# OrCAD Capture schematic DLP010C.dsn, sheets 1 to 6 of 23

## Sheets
1 PAGE23- IMPORTANT NOTICE
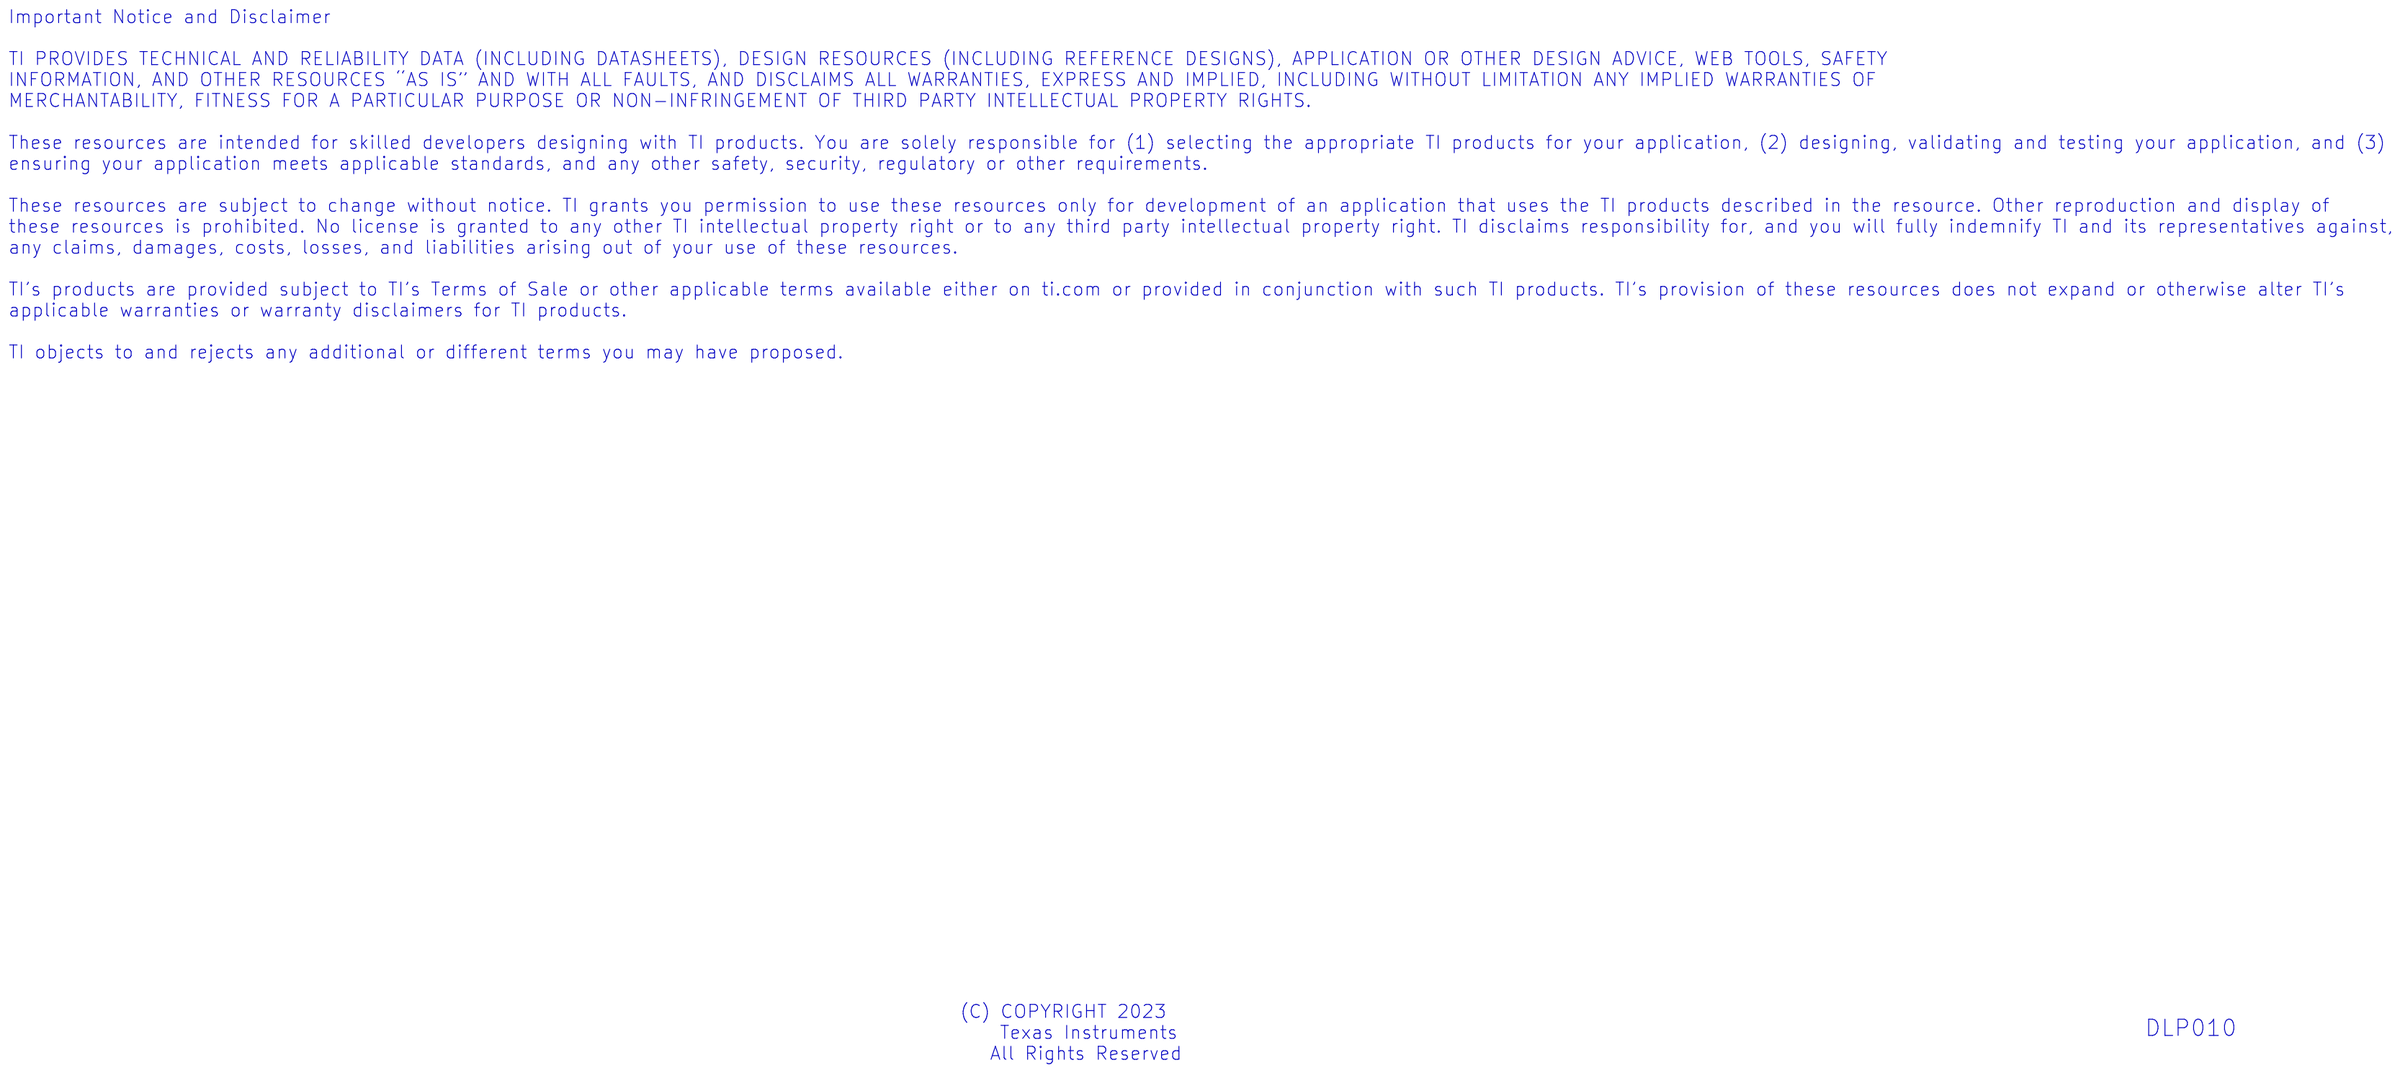
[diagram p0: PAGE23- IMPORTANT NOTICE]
2 PAGE 01 - TITLE PAGE: title: DLP010A - DLPLCRC410EVM Board
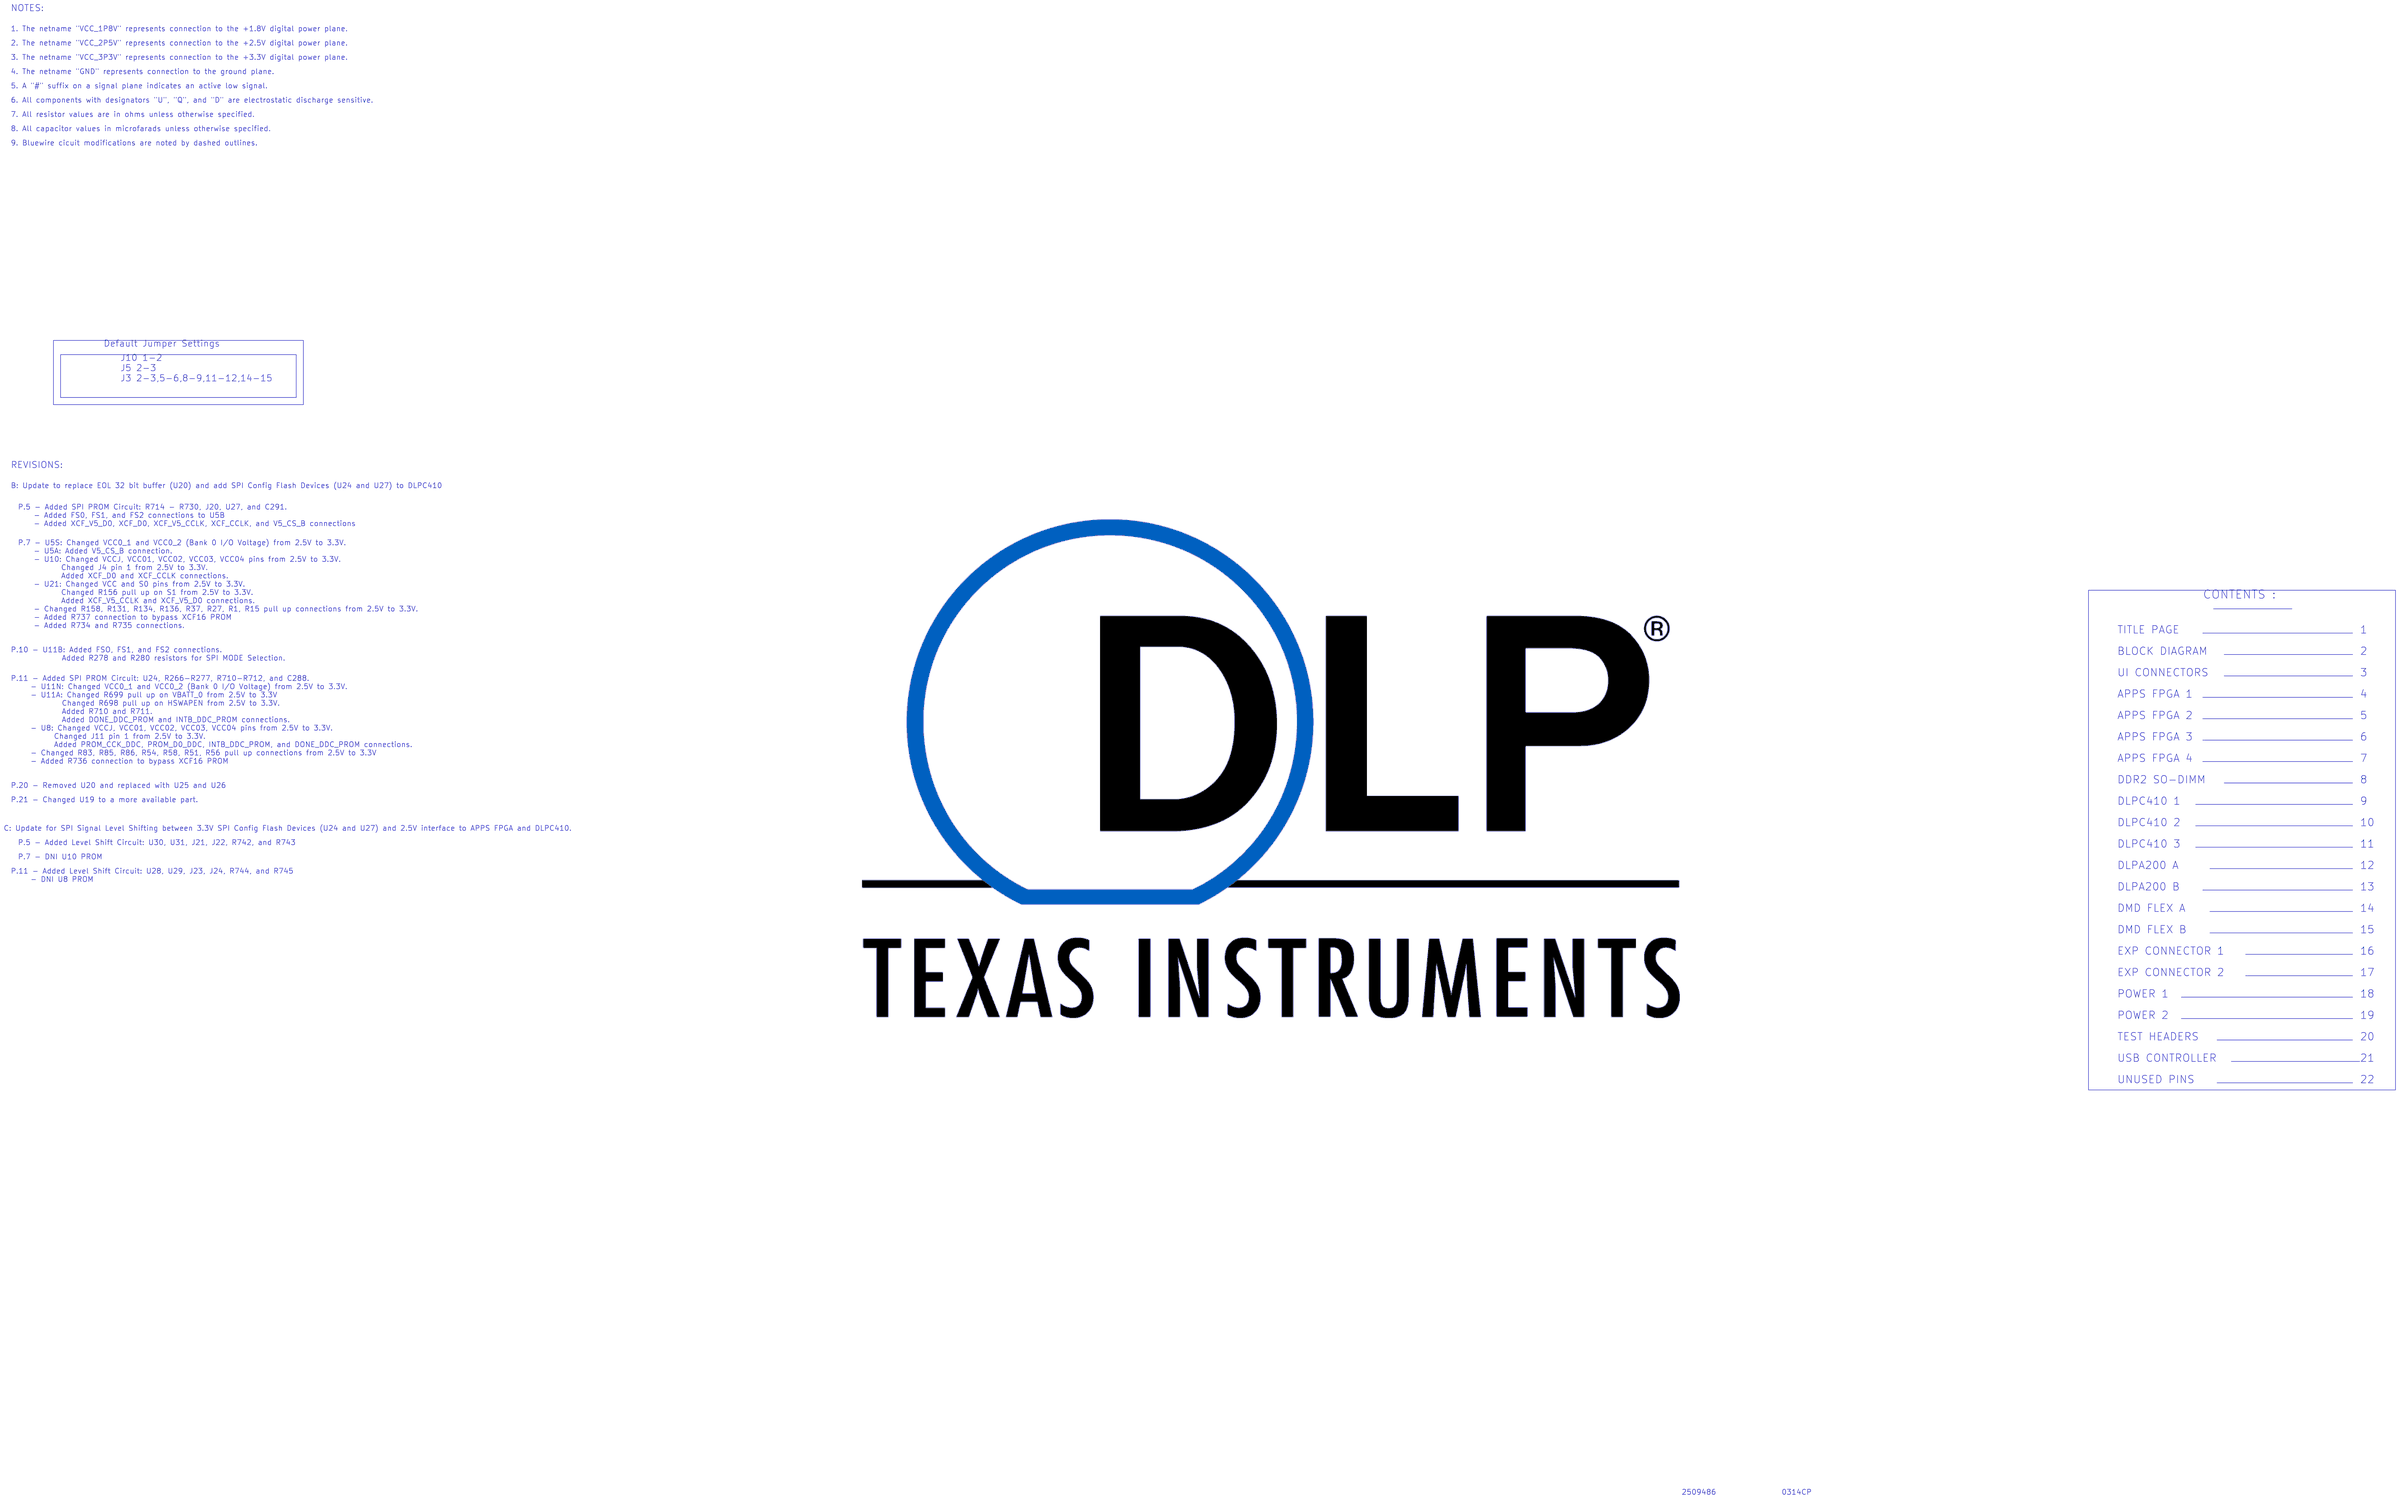
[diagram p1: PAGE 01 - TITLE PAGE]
3 PAGE 02 - BLOCK DIAGRAM
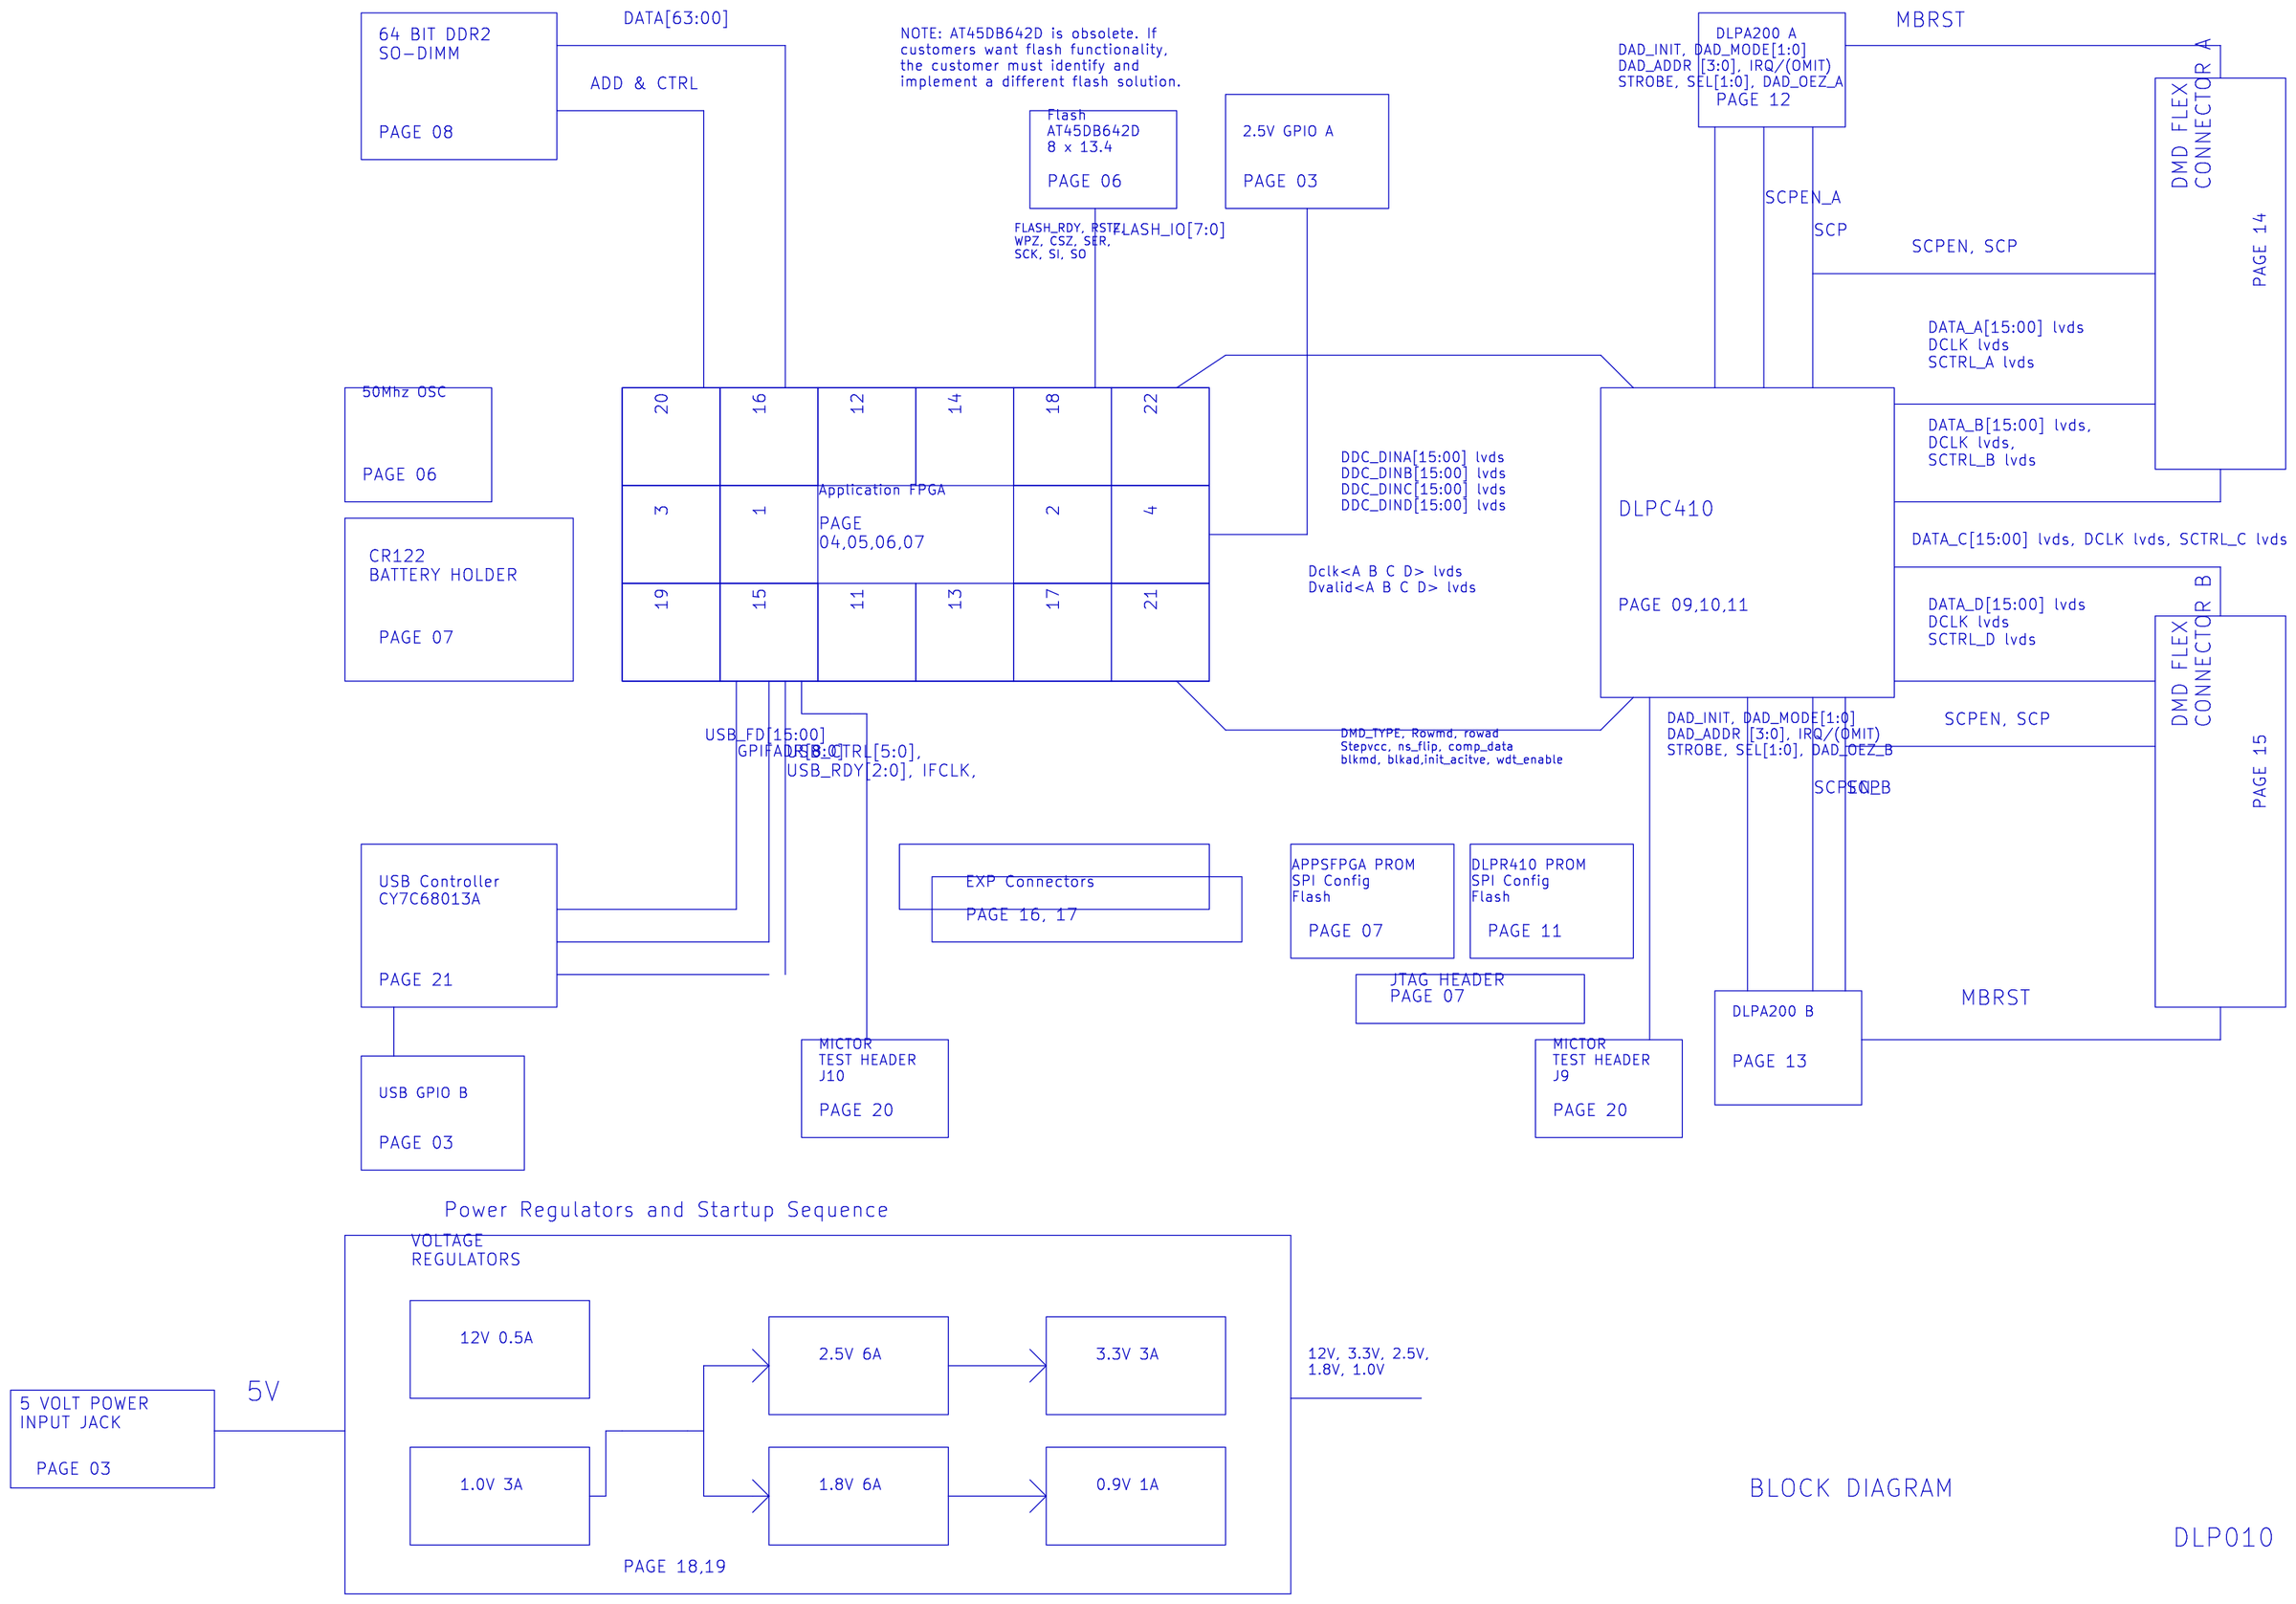
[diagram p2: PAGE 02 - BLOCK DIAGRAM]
4 PAGE 03 - UI CONNECTORS: size Custom
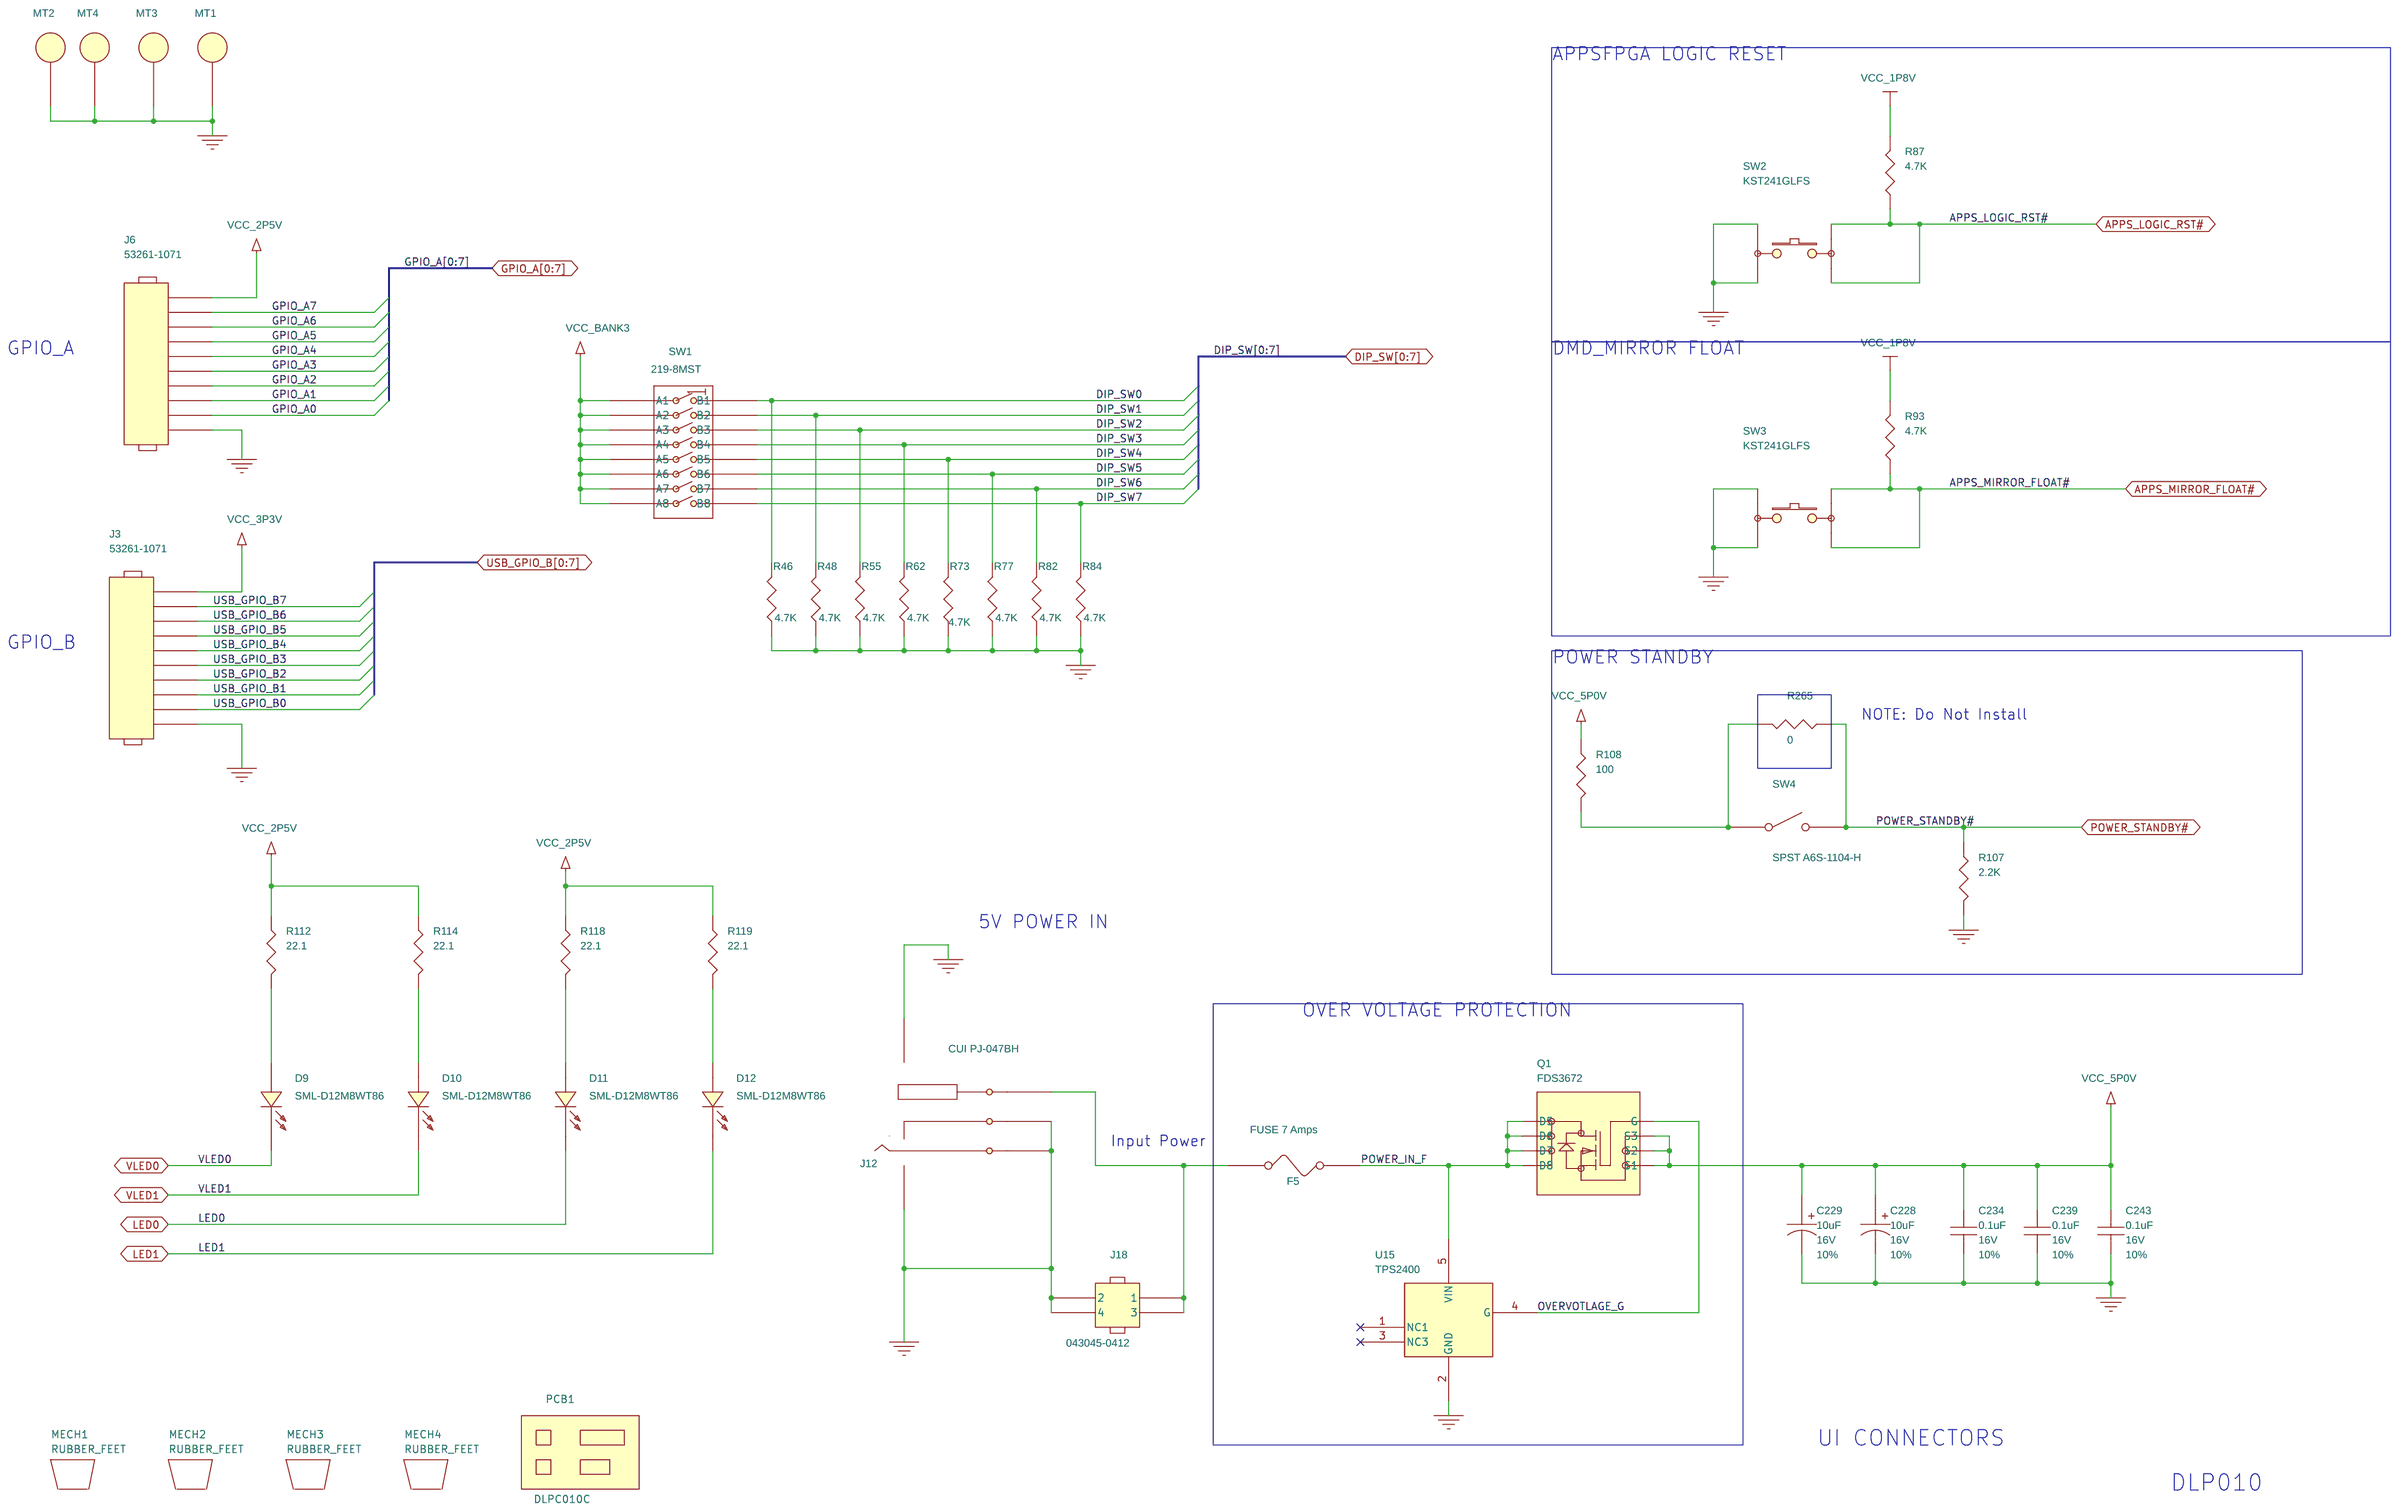
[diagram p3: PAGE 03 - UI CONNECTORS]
5 PAGE 04 - VIRTEX5 - 1: size Custom
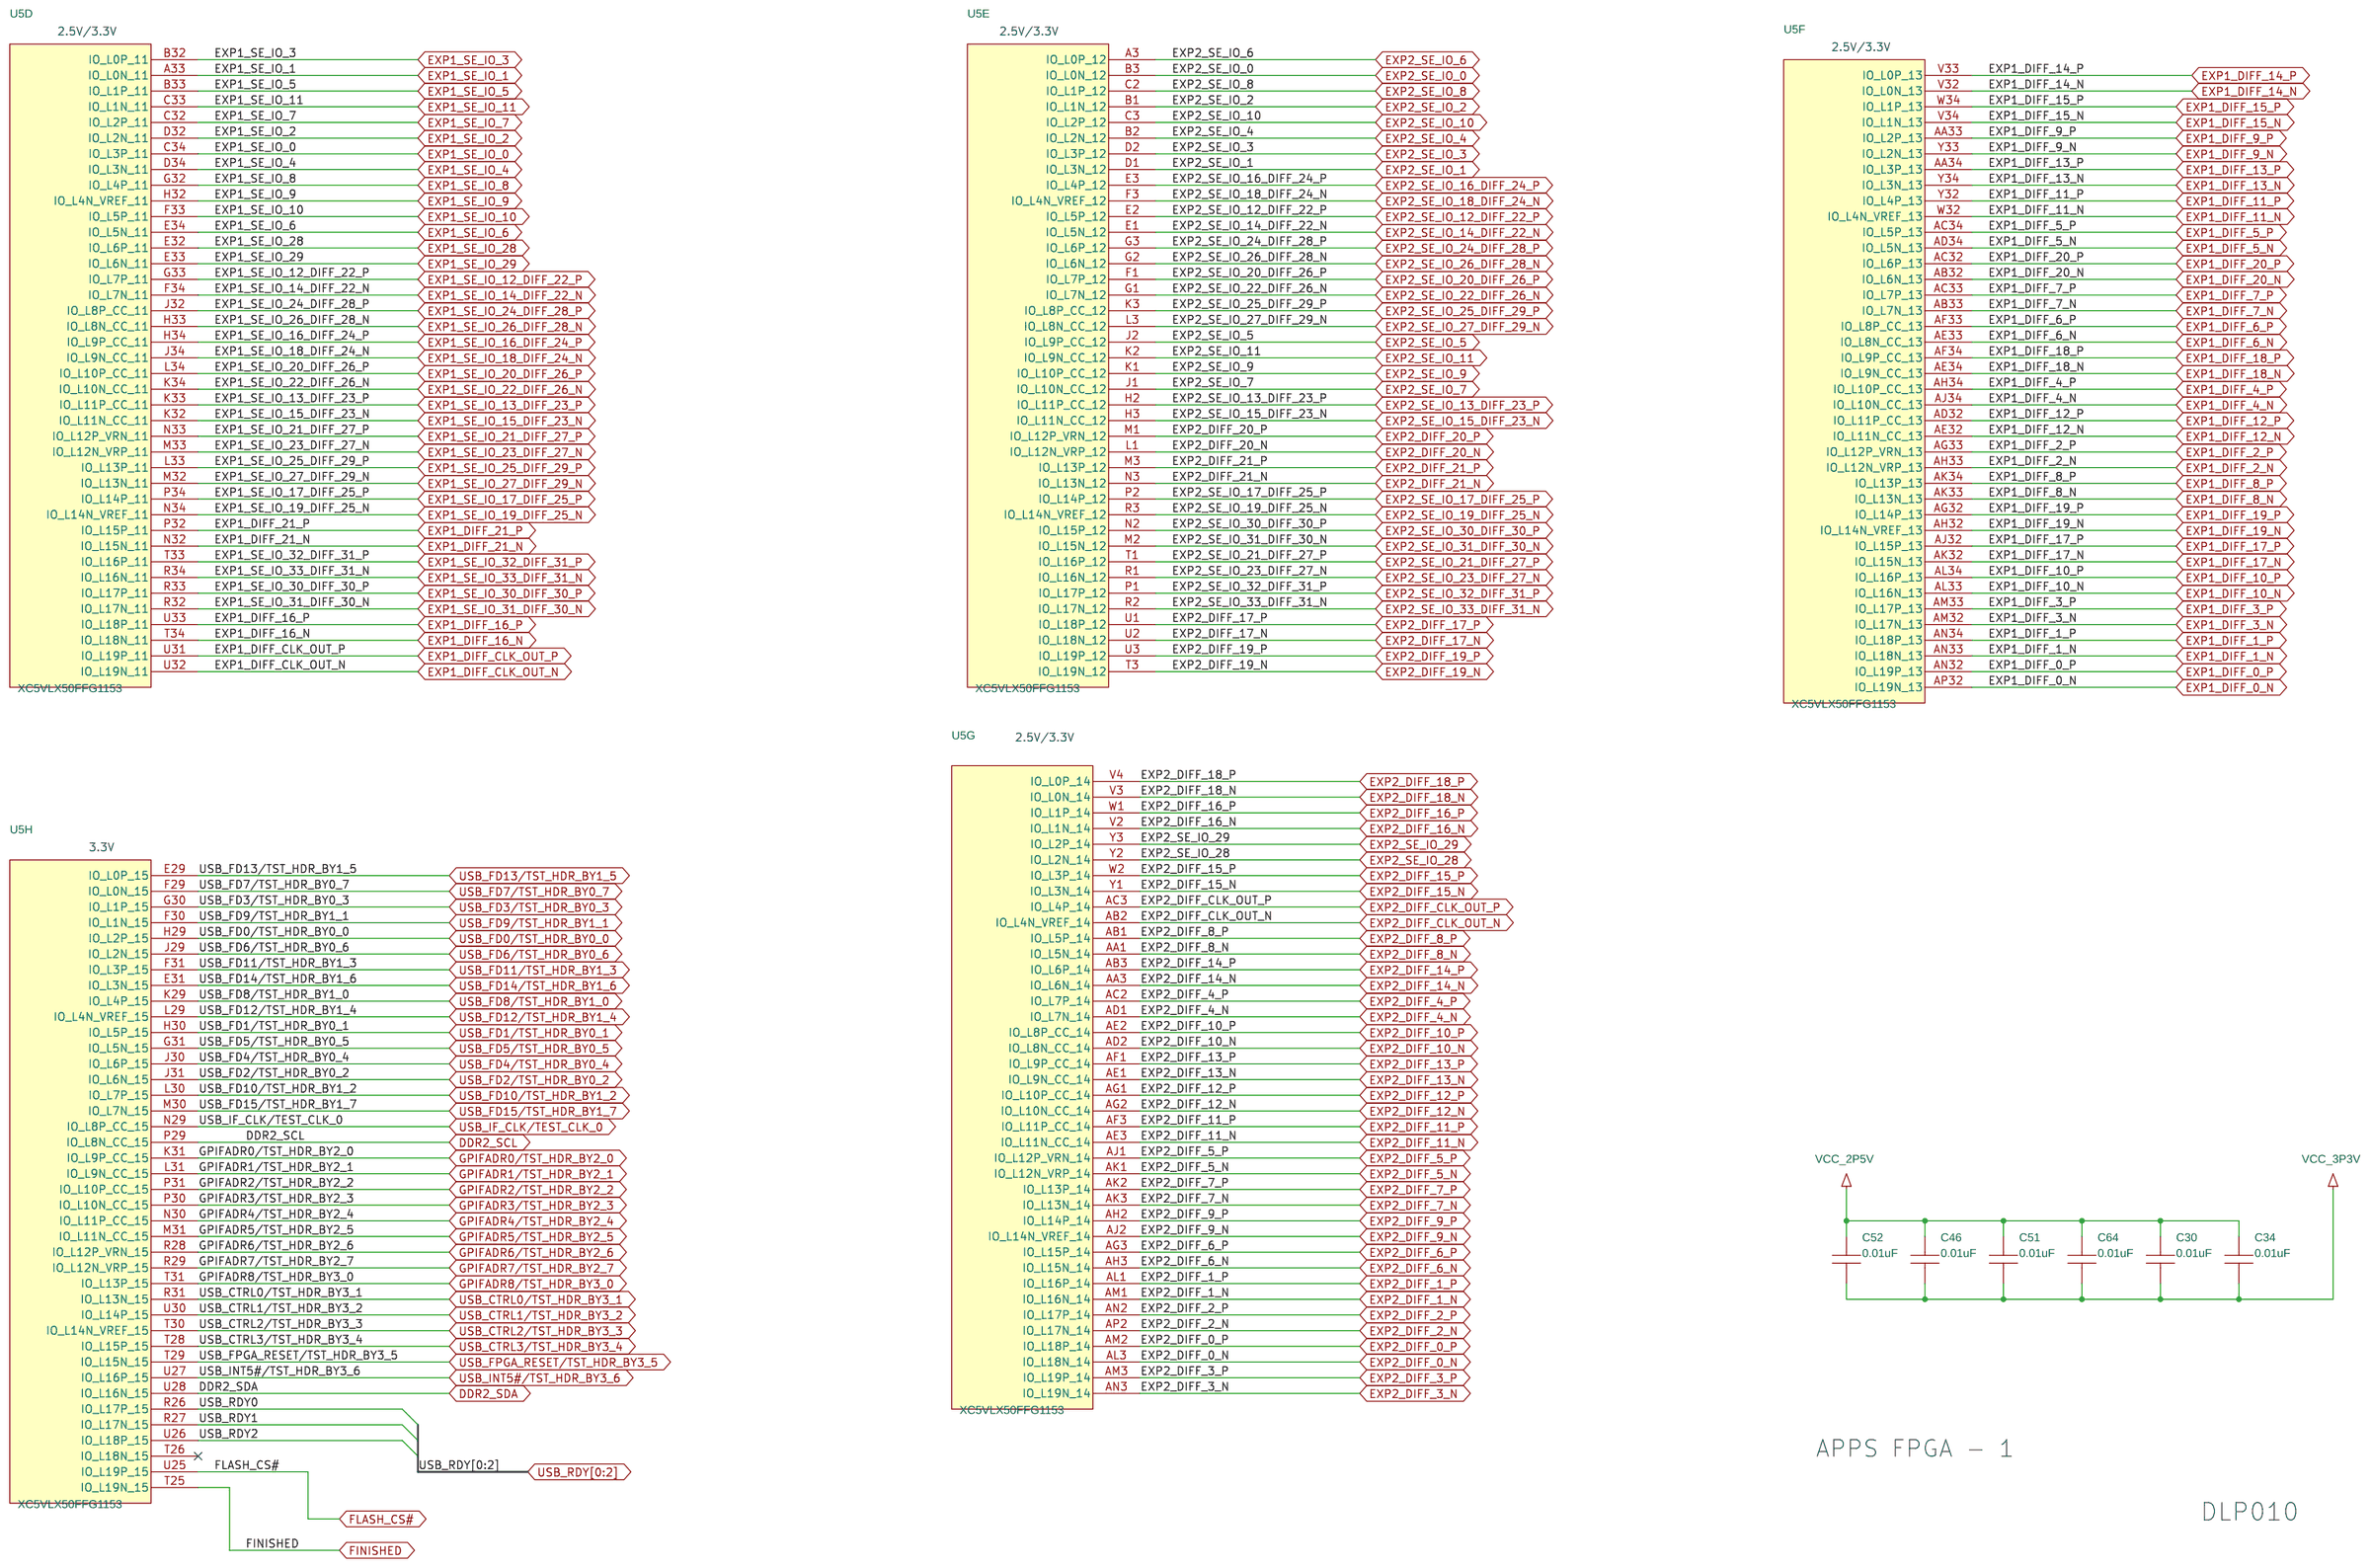
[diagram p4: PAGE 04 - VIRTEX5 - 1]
6 PAGE 05 - VIRTEX5 - 2: size Custom
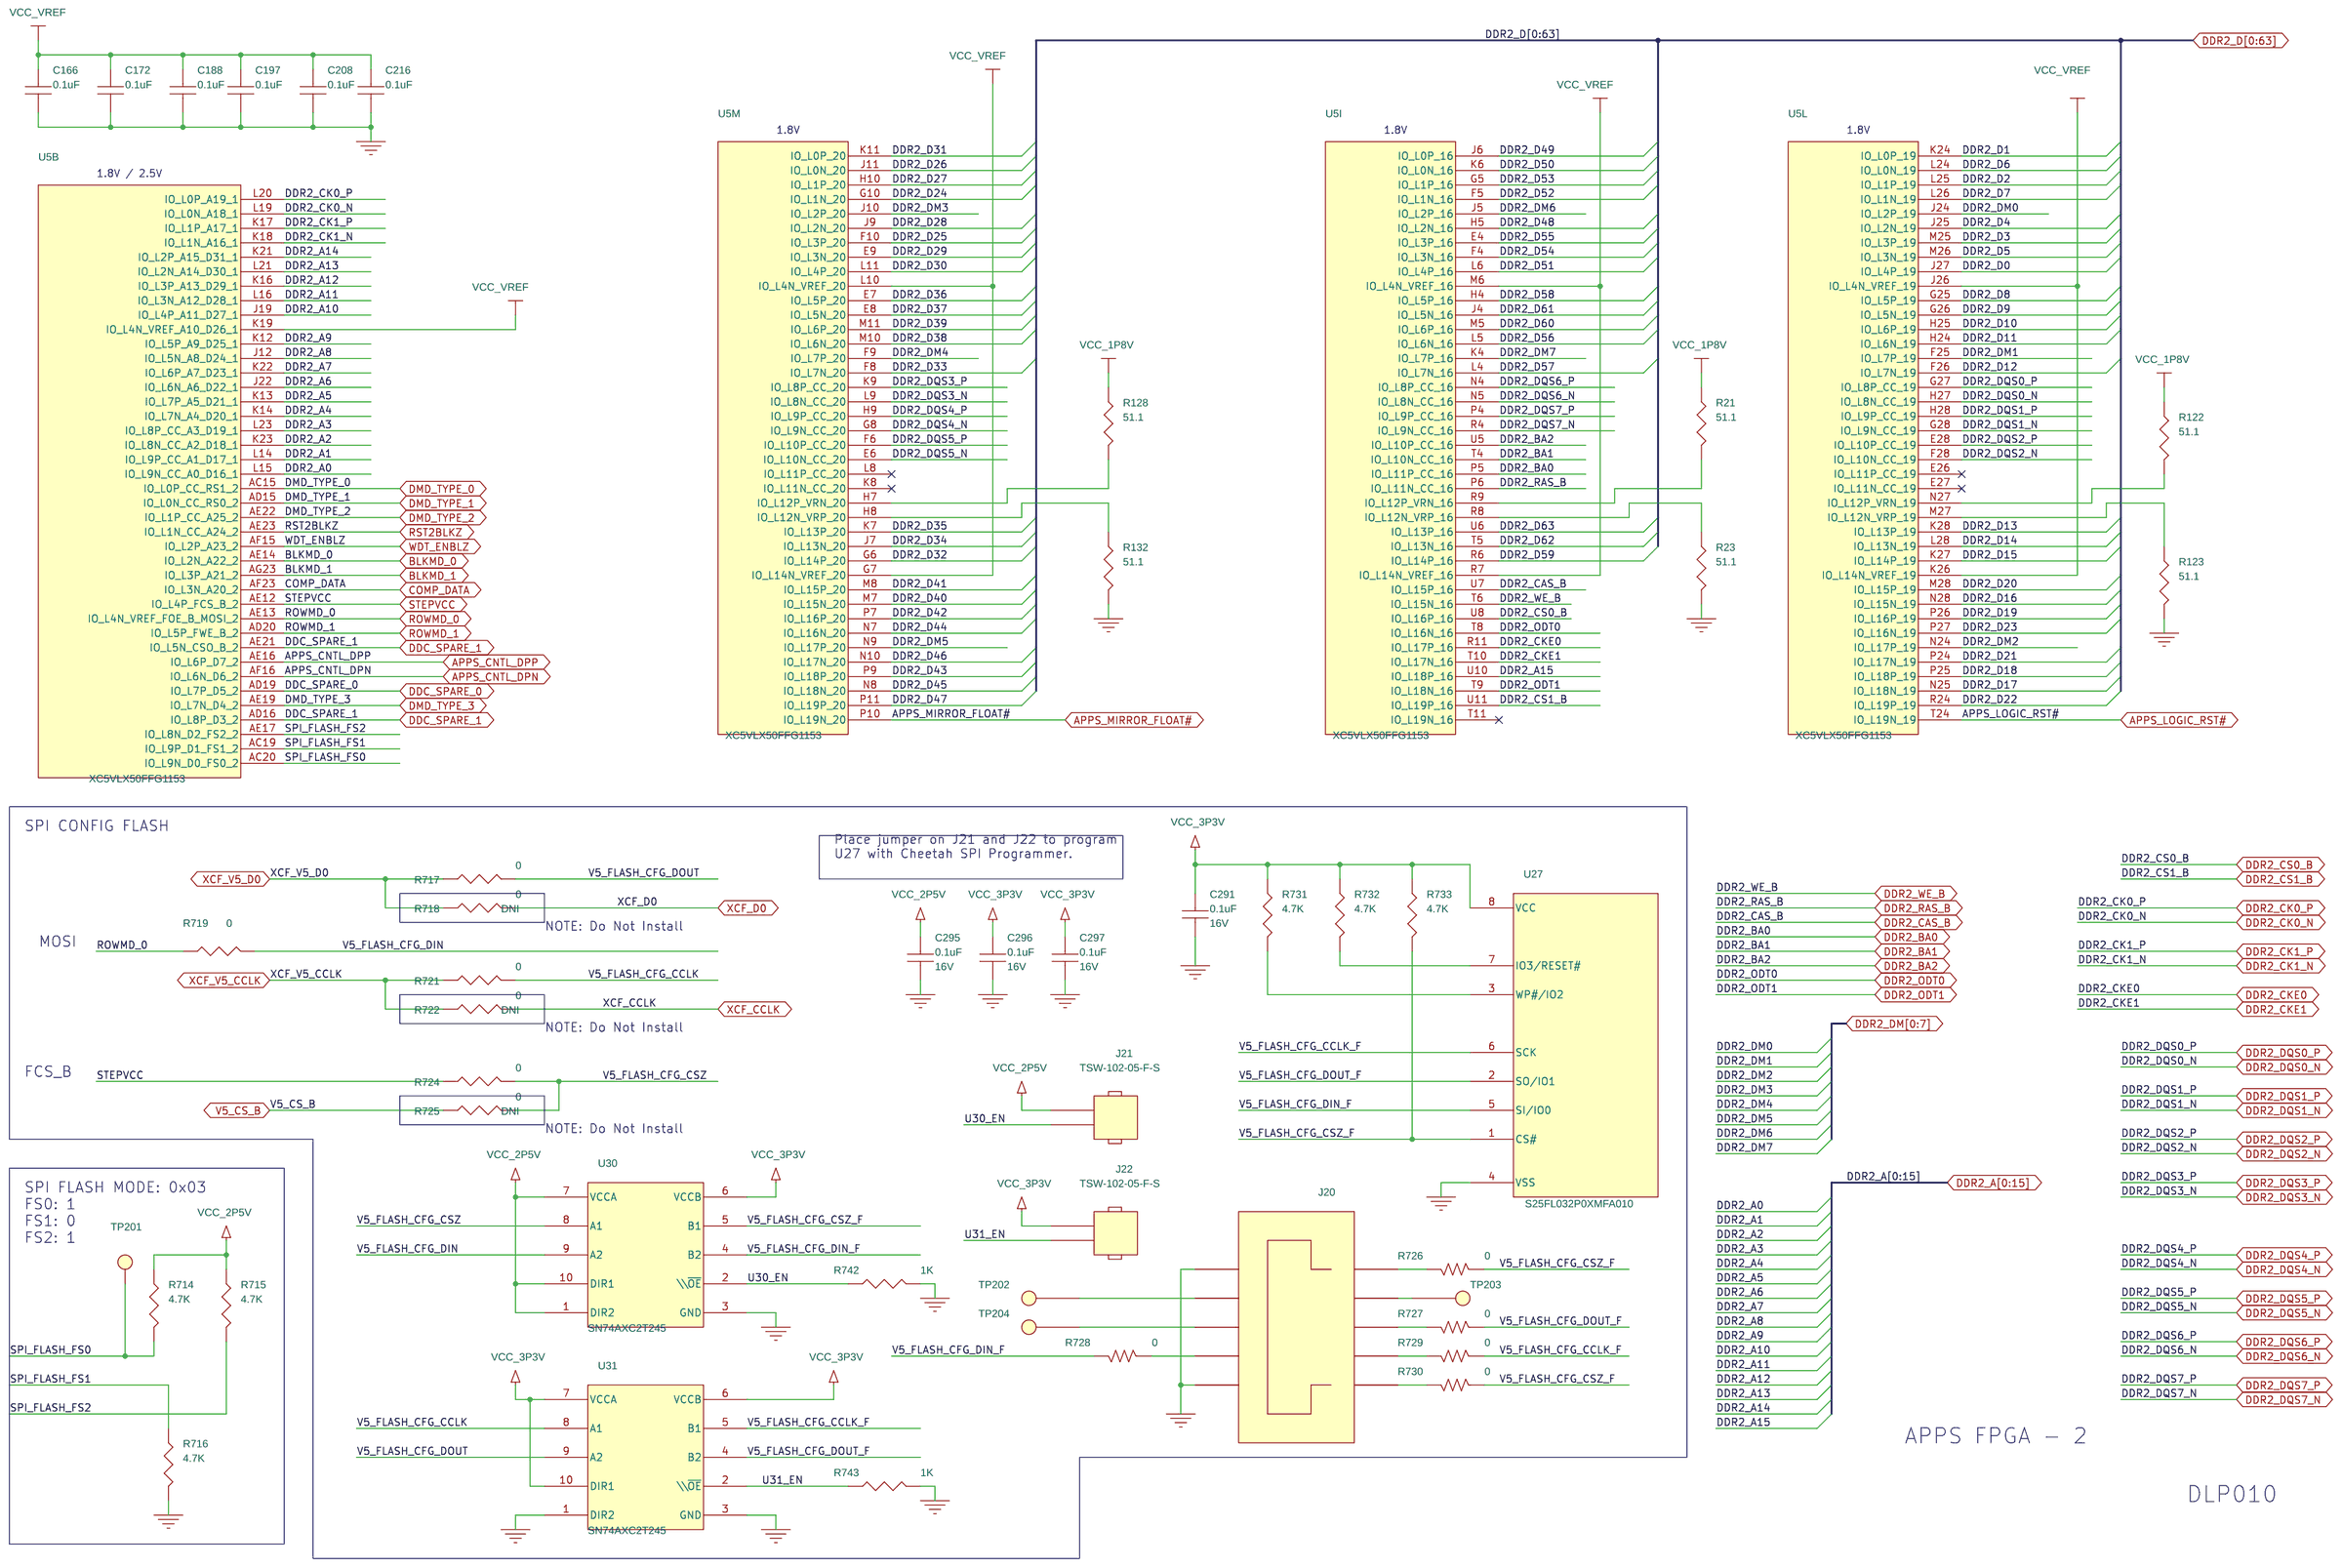
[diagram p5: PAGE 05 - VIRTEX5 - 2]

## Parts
sheet PAGE 03 - UI CONNECTORS
C228  10uF  [tant_a]
C229  10uF  [tant_a]
C234  0.1uF  [0603]
C239  0.1uF  [0603]
C243  0.1uF  [0603]
D9  SML-D12M8WT86  [sm_led_0603]
D10  SML-D12M8WT86  [sm_led_0603]
D11  SML-D12M8WT86  [sm_led_0603]
D12  SML-D12M8WT86  [sm_led_0603]
F5  FUSE 7 Amps  [sm_littelfuse_mrl]
J3  53261-1071  [sm_conn_molx_532611071]
J6  53261-1071  [sm_conn_molx_532611071]
J12  CUI PJ-047BH  [CUI_PJ-047BH]
J18  043045-0412  [MOLEX_43045-0412]
MECH1  RUBBER_FEET
MECH2  RUBBER_FEET
MECH3  RUBBER_FEET
MECH4  RUBBER_FEET
MT1  MOUNT_HOLE  [th_mth_140d250p]
MT2  MOUNT_HOLE  [th_mth_140d250p]
MT3  MOUNT_HOLE  [th_mth_140d250p]
MT4  MOUNT_HOLE  [th_mth_140d250p]
PCB1  DLPC010C
Q1  FDS3672  [8soic]
R46  4.7K  [0603]
R48  4.7K  [0603]
R55  4.7K  [0603]
R62  4.7K  [0603]
R73  4.7K  [0603]
R77  4.7K  [0603]
R82  4.7K  [0603]
R84  4.7K  [0603]
R87  4.7K  [0603]
R93  4.7K  [0603]
R107  2.2K  [0603]
R108  100  [0402]
R112  22.1  [0603]
R114  22.1  [0603]
R118  22.1  [0603]
R119  22.1  [0603]
R265  0  [0603]
SW1  219-8MST  [16SMT]
SW2  KST241GLFS  [4PSO]
SW3  KST241GLFS  [4PSO]
SW4  SPST A6S-1104-H  [OMRON_A6S-1104-H]
U15  TPS2400  [sot23-5]
sheet PAGE 04 - VIRTEX5 - 1
C30  0.01uF  [0603]
C34  0.01uF  [0603]
C46  0.01uF  [0603]
C51  0.01uF  [0603]
C52  0.01uF  [0603]
C64  0.01uF  [0603]
sheet PAGE 05 - VIRTEX5 - 2
C166  0.1uF  [0603]
C172  0.1uF  [0603]
C188  0.1uF  [0603]
C197  0.1uF  [0603]
C208  0.1uF  [0603]
C216  0.1uF  [0603]
C291  0.1uF  [0603]
C295  0.1uF  [0603]
C296  0.1uF  [0603]
C297  0.1uF  [0603]
J20  SPIconn  [SAMTEC_TST-105-01-G-D]
J21  TSW-102-05-F-S  [jumper2]
J22  TSW-102-05-F-S  [jumper2]
R21  51.1  [0603]
R23  51.1  [0603]
R122  51.1  [0603]
R123  51.1  [0603]
R128  51.1  [0603]
R132  51.1  [0603]
R714  4.7K  [0603]
R715  4.7K  [0603]
R716  4.7K  [0603]
R717  0  [0603]
R718  0  [0603]
R719  0  [0603]
R721  0  [0603]
R722  0  [0603]
R724  0  [0603]
R725  0  [0603]
R726  0  [0603]
R727  0  [0603]
R728  0  [0603]
R729  0  [0603]
R730  0  [0603]
R731  4.7K  [0603]
R732  4.7K  [0603]
R733  4.7K  [0603]
R742  1K  [0603]
R743  1K  [0603]
TP201  T POINT R  [25MILSQPOST]
TP202  Testpoint_via  [TP121H71]
TP203  Testpoint_via  [TP121H71]
TP204  Testpoint_via  [TP121H71]
U27  S25FL032P0XMFA010  [SOIC127P790x216-8N]
U30  SN74AXC2T245  [QFN40P180X140X55-10N]
U31  SN74AXC2T245  [QFN40P180X140X55-10N]
sheet PAGE 07 - VIRTEX5 - 4
U5  XC5VLX50FFG1153  [sm_ff1153]  (sections A,B,C,D,E,F,G,H,I,J,K,L,M,N,O,P,Q,R,S,T,U)

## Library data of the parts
C228 C229 = CAP_POL: Manuf: AVX; PartNumber: TAJA106K016RNJ; ROOM: UI; Tolerance: 10%; Voltage: 16V
C234 C239 C243 = CAP_NP: Manuf: Kemet; PartNumber: C0603C104K4RACTU; ROOM: UI; Tolerance: 10%; Voltage: 16V
D9-D12 = LED: Manuf: ROHM; ROOM: UI
F5 = FUSE: Current: 7A; Manuf: Littelfuse; PartNumber: 0451007.MRL; ROOM: UI; Voltage: 65V
J3 J6 = HEADER_10_SM: Manuf: Molex; ROOM: UI
J12 = PJ1-022-SMT: Manuf: CUI; PartNumber: PJ-047BH
J18 = CONN_PWR_2x2-P: Manuf: Molex; PartNumber: 0430450412
MECH1-MECH4 = RubberFeet: Manuf: 3M; PartNumber: SJ61A4
MT1-MT4 = MOUNT_HOLE: DNI: DNI; Manuf: Not-a-part; Notes: DNI - Mounting Hole; PartNumber: Not-a-part; ROOM: UI
PCB1 = PCB1: PCB, DLP010C; Manuf: Any; PartNumber: DLP010C
Q1 = FDS3672: Manuf: Fairchild
R46 R48 R55 R62 R73 R77 R82 R84 R87 R93 = R_v2: Manuf: Panasonic; Part Number: ERJ-3GEYJ472V; PartNumber: ERJ-3GEYJ472V; ROOM: UI; Tolerance: %1; Vendor: PANASONIC
R107 = R_v2: Manuf: Panasonic; PartNumber: ERJ-3GEYJ103V; ROOM: Power; Tolerance: %1
R108 = R_v2: Manuf: Panasonic; PartNumber: ERJ-2RKF1000X; ROOM: V5
R112 R114 R118 R119 = R_v2: Manuf: Panasonic; PartNumber: ERJ-3EKF22R1V; ROOM: UI; Tolerance: %1
R265 = R_v2: DNI: DNI; Manuf: Panasonic; Notes: DNI; PartNumber: ERJ-3GEY0R00V; ROOM: USB; Tolerance: %1
SW1 = DFM-DIP-SW-8: Manuf: CTS; ROOM: UI; Vendor: CTS
SW2 SW3 = SW_PUSHBUTTON-SPST-2_SM: Manuf: C&K; ROOM: UI; Vendor: C&K
SW4 = SW_SPST: Manuf: Omron; PartNumber: A6S-1104-H
U15 = TPS2400: Manuf: Texas Instruments; PartNumber: TPS2400DBVT
C30 C34 C46 C51 C52 C64 = CAP_NP: Manuf: Kemet; PartNumber: C0603C103K5RACTU; ROOM: SODIMM; Tolerance: 10%; Voltage: 50V
C166 C172 C188 C197 C208 C216 = CAP_NP: Manuf: Kemet; PartNumber: C0603C104K4RACTU; ROOM: V5; Tolerance: 10%; Voltage: 16V
C291 C295-C297 = CAP_NP: Manuf: Kemet; PartNumber: C0603C104K4RACTU; ROOM: DDC4100; Tolerance: 10%; Voltage: 16V
J20 = SPI_Connector: MFG: Samtec; Manuf: Samtec; PART NUMBER: TST-105-01-G-D; PartNumber: TST-105-01-G-D
J21 J22 = HEADER_2: Manuf: Samtec; PartNumber: TSW-102-07-F-S; ROOM: USB
R21 R23 R122 R123 R128 R132 = R_v2: Manuf: Panasonic; PartNumber: ERJ-3EKF51R1V; ROOM: V5; Tolerance: %1
R714-R716 R731-R733 = R_v2: Manuf: Panasonic; PartNumber: ERJ-3GEYJ472V; ROOM: DDC4100; Tolerance: %1
R717 R719 R721 R724 = R_v2: Manuf: Panasonic; PartNumber: ERJ-3GEY0R00V; ROOM: DDC4100; Tolerance: %1
R718 R722 R725 = R_v2: DNI: DNI; Manuf: Panasonic; Notes: DNI; PartNumber: ERJ-3GEY0R00V; ROOM: DDC4100; Tolerance: %1
R726-R730 = R: DigiKey Part Number: 1276-3480-1-ND; MFG: Vishay Dale; Manuf: Vishay Dale; PART NUMBER: CRCW06030000Z0EAC; PartNumber: CRCW06030000Z0EAC; Rating: 0.1 W
R742 R743 = R_v2: Manuf: Panasonic; PartNumber: ERJ-3GEYJ102V; Tolerance: %1
TP201 = T_POINT_R: DNI: DNI; Manuf: Not-a-part; PartNumber: Not-a-part; ROOM: ECP2
TP202-TP204 = Testpoint: DNI: DNI; MFG: Not-a-part; Manuf: Not-a-part; Notes: 28mil_via; PART NUMBER: Not-a-part; PartNumber: Not-a-part
U27 = S25FL128LAGMFM010: IC FLASH 32MBIT SPI/QUAD 8SOIC; Digikey Part Number: 428-4396-ND; MFG: Infineon Technologies; Manuf: Infineon Technologies; Manufacturer: Cypress
U30 U31 = SN74AXC2T245: MFG: Texas Instruments; Manuf: Texas Instruments; PartNumber: SN74AXC2T245RSWR
U5 = XC5VLX50FF1153_13: Manuf: xilinx; PartNumber: XC5VLX50-1FFG1153C; ROOM: V5

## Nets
GND: C166.2 C172.2 C188.2 C197.2 C208.2 C216.2 C228.2 C229.2 C234.2 C239.2 C243.2 C291.2 C295.2 C296.2 C297.2 J3.10 J6.10 J12.2 J12.3 J12.4 J12.5 J18.1(2) J18.2(4) J20.2 J20.10 MT1.1 MT2.1 MT3.1 MT4.1 R23.2 R46.1 R48.1 R55.1 R62.1 R73.1 R77.1 R82.1 R84.1 R107.2 R123.2 R132.2 R716.2 R742.2 R743.2 SW2.1 SW2.2 SW3.1 SW3.2 U15.2(GND) U27.4(VSS) U30.3(GND) U31.1(DIR2) U31.3(GND) ; also on sheet 7 8 9 10 11 12 13 14 15 16 17 18 19 20 21 22
V5_CS_B: R725.1 ; also on sheet 8
V5_FLASH_CFG_CCLK: R721.2 U31.8(A1)
V5_FLASH_CFG_CCLK_F: R729.1 U27.6(SCK) U31.5(B1)
V5_FLASH_CFG_CSZ: R724.2 R725.2 U30.8(A1)
V5_FLASH_CFG_CSZ_F: R726.1 R730.1 R733.2 U27.1(CS#) U30.5(B1)
V5_FLASH_CFG_DIN: R719.2 U30.9(A2)
V5_FLASH_CFG_DIN_F: R728.2 U27.5(SI/IO0) U30.4(B2)
V5_FLASH_CFG_DOUT: R717.2 U31.9(A2)
V5_FLASH_CFG_DOUT_F: R727.1 U27.2(SO/IO1) U31.4(B2)
VCC_1P8V: R21.1 R87.2 R93.2 R122.1 R128.1 ; also on sheet 8 9 12 19
VCC_2P5V: C30.1 C34.1 C46.1 C51.1 C52.1 C64.1 C295.1 J6.1 J21.1 R112.1 R114.1 R118.1 R119.1 R714.1 R715.1 U30.1(DIR2) U30.7(VCCA) U30.10(DIR1) ; also on sheet 7 8 10 11 12 13 14 17 18 19
VCC_3P3V: C30.2 C34.2 C46.2 C51.2 C52.2 C64.2 C291.1 C296.1 C297.1 J3.1 J22.1 R731.1 R732.1 R733.1 U27.8(VCC) U30.6(VCCB) U31.6(VCCB) U31.7(VCCA) U31.10(DIR1) ; also on sheet 7 8 9 12 15 16 17 18 19 21 22
VCC_5P0V: C228.1 C229.1 C234.1 C239.1 C243.1 Q1.1(S1) Q1.2(S2) Q1.3(S3) R108.1 ; also on sheet 19 20
VCC_BANK3: SW1.1(A1) SW1.2(A2) SW1.3(A3) SW1.4(A4) SW1.5(A5) SW1.6(A6) SW1.7(A7) SW1.8(A8) ; also on sheet 7 8
VCC_VREF: C166.1 C172.1 C188.1 C197.1 C208.1 C216.1 U5.G7(IO_L14N_VREF_20) U5.J26(IO_L4N_VREF_19) U5.K19(IO_L4N_VREF_A10_D26_1) U5.K26(IO_L14N_VREF_19) U5.L10(IO_L4N_VREF_20) U5.M6(IO_L4N_VREF_16) U5.R7(IO_L14N_VREF_16) ; also on sheet 9 19
APPS_CNTL_DPN: U5.AF16(IO_L6N_D6_2) ; also on sheet 10
APPS_CNTL_DPP: U5.AE16(IO_L6P_D7_2) ; also on sheet 10
APPS_LOGIC_RST#: R87.1 SW2.3 SW2.4 U5.T24(IO_L19N_19)
APPS_MIRROR_FLOAT#: R93.1 SW3.3 SW3.4 U5.P10(IO_L19N_20)
BLKMD_0: U5.AE14(IO_L2N_A22_2) ; also on sheet 11
BLKMD_1: U5.AG23(IO_L3P_A21_2) ; also on sheet 11
COMP_DATA: U5.AF23(IO_L3N_A20_2) ; also on sheet 11
DDC_SPARE_0: U5.AD19(IO_L7P_D5_2) ; also on sheet 11
DDC_SPARE_1: U5.AD16(IO_L8P_D3_2) U5.AE21(IO_L5N_CSO_B_2) ; also on sheet 11
DDR2_A0: U5.L15(IO_L9N_CC_A0_D16_1) ; also on sheet 9
DDR2_A1: U5.L14(IO_L9P_CC_A1_D17_1) ; also on sheet 9
DDR2_A2: U5.K23(IO_L8N_CC_A2_D18_1) ; also on sheet 9
DDR2_A3: U5.L23(IO_L8P_CC_A3_D19_1) ; also on sheet 9
DDR2_A4: U5.K14(IO_L7N_A4_D20_1) ; also on sheet 9
DDR2_A5: U5.K13(IO_L7P_A5_D21_1) ; also on sheet 9
DDR2_A6: U5.J22(IO_L6N_A6_D22_1) ; also on sheet 9
DDR2_A7: U5.K22(IO_L6P_A7_D23_1) ; also on sheet 9
DDR2_A8: U5.J12(IO_L5N_A8_D24_1) ; also on sheet 9
DDR2_A9: U5.K12(IO_L5P_A9_D25_1) ; also on sheet 9
DDR2_A10: U5.J19(IO_L4P_A11_D27_1) ; also on sheet 9
DDR2_A11: U5.L16(IO_L3N_A12_D28_1) ; also on sheet 9
DDR2_A12: U5.K16(IO_L3P_A13_D29_1) ; also on sheet 9
DDR2_A13: U5.L21(IO_L2N_A14_D30_1) ; also on sheet 9
DDR2_A14: U5.K21(IO_L2P_A15_D31_1) ; also on sheet 9
DDR2_A15: U5.U10(IO_L18P_16) ; also on sheet 9
DDR2_BA0: U5.P5(IO_L11P_CC_16) ; also on sheet 9
DDR2_BA1: U5.T4(IO_L10N_CC_16) ; also on sheet 9
DDR2_BA2: U5.U5(IO_L10P_CC_16) ; also on sheet 9
DDR2_CAS_B: U5.U7(IO_L15P_16) ; also on sheet 9
DDR2_CK0_N: U5.L19(IO_L0N_A18_1) ; also on sheet 9
DDR2_CK0_P: U5.L20(IO_L0P_A19_1) ; also on sheet 9
DDR2_CK1_N: U5.K18(IO_L1N_A16_1) ; also on sheet 9
DDR2_CK1_P: U5.K17(IO_L1P_A17_1) ; also on sheet 9
DDR2_CKE0: U5.R11(IO_L17P_16) ; also on sheet 9
DDR2_CKE1: U5.T10(IO_L17N_16) ; also on sheet 9
DDR2_CS0_B: U5.U8(IO_L16P_16) ; also on sheet 9
DDR2_CS1_B: U5.U11(IO_L19P_16) ; also on sheet 9
DDR2_D0: U5.J27(IO_L4P_19) ; also on sheet 9
DDR2_D1: U5.K24(IO_L0P_19) ; also on sheet 9
DDR2_D2: U5.L25(IO_L1P_19) ; also on sheet 9
DDR2_D3: U5.M25(IO_L3P_19) ; also on sheet 9
DDR2_D4: U5.J25(IO_L2N_19) ; also on sheet 9
DDR2_D5: U5.M26(IO_L3N_19) ; also on sheet 9
DDR2_D6: U5.L24(IO_L0N_19) ; also on sheet 9
DDR2_D7: U5.L26(IO_L1N_19) ; also on sheet 9
DDR2_D8: U5.G25(IO_L5P_19) ; also on sheet 9
DDR2_D9: U5.G26(IO_L5N_19) ; also on sheet 9
DDR2_D10: U5.H25(IO_L6P_19) ; also on sheet 9
DDR2_D11: U5.H24(IO_L6N_19) ; also on sheet 9
DDR2_D12: U5.F26(IO_L7N_19) ; also on sheet 9
DDR2_D13: U5.K28(IO_L13P_19) ; also on sheet 9
DDR2_D14: U5.L28(IO_L13N_19) ; also on sheet 9
DDR2_D15: U5.K27(IO_L14P_19) ; also on sheet 9
DDR2_D16: U5.N28(IO_L15N_19) ; also on sheet 9
DDR2_D17: U5.N25(IO_L18N_19) ; also on sheet 9
DDR2_D18: U5.P25(IO_L18P_19) ; also on sheet 9
DDR2_D19: U5.P26(IO_L16P_19) ; also on sheet 9
DDR2_D20: U5.M28(IO_L15P_19) ; also on sheet 9
DDR2_D21: U5.P24(IO_L17N_19) ; also on sheet 9
DDR2_D22: U5.R24(IO_L19P_19) ; also on sheet 9
DDR2_D23: U5.P27(IO_L16N_19) ; also on sheet 9
DDR2_D24: U5.G10(IO_L1N_20) ; also on sheet 9
DDR2_D25: U5.F10(IO_L3P_20) ; also on sheet 9
DDR2_D26: U5.J11(IO_L0N_20) ; also on sheet 9
DDR2_D27: U5.H10(IO_L1P_20) ; also on sheet 9
DDR2_D28: U5.J9(IO_L2N_20) ; also on sheet 9
DDR2_D29: U5.E9(IO_L3N_20) ; also on sheet 9
DDR2_D30: U5.L11(IO_L4P_20) ; also on sheet 9
DDR2_D31: U5.K11(IO_L0P_20) ; also on sheet 9
DDR2_D32: U5.G6(IO_L14P_20) ; also on sheet 9
DDR2_D33: U5.F8(IO_L7N_20) ; also on sheet 9
DDR2_D34: U5.J7(IO_L13N_20) ; also on sheet 9
DDR2_D35: U5.K7(IO_L13P_20) ; also on sheet 9
DDR2_D36: U5.E7(IO_L5P_20) ; also on sheet 9
DDR2_D37: U5.E8(IO_L5N_20) ; also on sheet 9
DDR2_D38: U5.M10(IO_L6N_20) ; also on sheet 9
DDR2_D39: U5.M11(IO_L6P_20) ; also on sheet 9
DDR2_D40: U5.M7(IO_L15N_20) ; also on sheet 9
DDR2_D41: U5.M8(IO_L15P_20) ; also on sheet 9
DDR2_D42: U5.P7(IO_L16P_20) ; also on sheet 9
DDR2_D43: U5.P9(IO_L18P_20) ; also on sheet 9
DDR2_D44: U5.N7(IO_L16N_20) ; also on sheet 9
DDR2_D45: U5.N8(IO_L18N_20) ; also on sheet 9
DDR2_D46: U5.N10(IO_L17N_20) ; also on sheet 9
DDR2_D47: U5.P11(IO_L19P_20) ; also on sheet 9
DDR2_D48: U5.H5(IO_L2N_16) ; also on sheet 9
DDR2_D49: U5.J6(IO_L0P_16) ; also on sheet 9
DDR2_D50: U5.K6(IO_L0N_16) ; also on sheet 9
DDR2_D51: U5.L6(IO_L4P_16) ; also on sheet 9
DDR2_D52: U5.F5(IO_L1N_16) ; also on sheet 9
DDR2_D53: U5.G5(IO_L1P_16) ; also on sheet 9
DDR2_D54: U5.F4(IO_L3N_16) ; also on sheet 9
DDR2_D55: U5.E4(IO_L3P_16) ; also on sheet 9
DDR2_D56: U5.L5(IO_L6N_16) ; also on sheet 9
DDR2_D57: U5.L4(IO_L7N_16) ; also on sheet 9
DDR2_D58: U5.H4(IO_L5P_16) ; also on sheet 9
DDR2_D59: U5.R6(IO_L14P_16) ; also on sheet 9
DDR2_D60: U5.M5(IO_L6P_16) ; also on sheet 9
DDR2_D61: U5.J4(IO_L5N_16) ; also on sheet 9
DDR2_D62: U5.T5(IO_L13N_16) ; also on sheet 9
DDR2_D63: U5.U6(IO_L13P_16) ; also on sheet 9
DDR2_DM0: U5.J24(IO_L2P_19) ; also on sheet 9
DDR2_DM1: U5.F25(IO_L7P_19) ; also on sheet 9
DDR2_DM2: U5.N24(IO_L17P_19) ; also on sheet 9
DDR2_DM3: U5.J10(IO_L2P_20) ; also on sheet 9
DDR2_DM4: U5.F9(IO_L7P_20) ; also on sheet 9
DDR2_DM5: U5.N9(IO_L17P_20) ; also on sheet 9
DDR2_DM6: U5.J5(IO_L2P_16) ; also on sheet 9
DDR2_DM7: U5.K4(IO_L7P_16) ; also on sheet 9
DDR2_DQS0_N: U5.H27(IO_L8N_CC_19) ; also on sheet 9
DDR2_DQS0_P: U5.G27(IO_L8P_CC_19) ; also on sheet 9
DDR2_DQS1_N: U5.G28(IO_L9N_CC_19) ; also on sheet 9
DDR2_DQS1_P: U5.H28(IO_L9P_CC_19) ; also on sheet 9
DDR2_DQS2_N: U5.F28(IO_L10N_CC_19) ; also on sheet 9
DDR2_DQS2_P: U5.E28(IO_L10P_CC_19) ; also on sheet 9
DDR2_DQS3_N: U5.L9(IO_L8N_CC_20) ; also on sheet 9
DDR2_DQS3_P: U5.K9(IO_L8P_CC_20) ; also on sheet 9
DDR2_DQS4_N: U5.G8(IO_L9N_CC_20) ; also on sheet 9
DDR2_DQS4_P: U5.H9(IO_L9P_CC_20) ; also on sheet 9
DDR2_DQS5_N: U5.E6(IO_L10N_CC_20) ; also on sheet 9
DDR2_DQS5_P: U5.F6(IO_L10P_CC_20) ; also on sheet 9
DDR2_DQS6_N: U5.N5(IO_L8N_CC_16) ; also on sheet 9
DDR2_DQS6_P: U5.N4(IO_L8P_CC_16) ; also on sheet 9
DDR2_DQS7_N: U5.R4(IO_L9N_CC_16) ; also on sheet 9
DDR2_DQS7_P: U5.P4(IO_L9P_CC_16) ; also on sheet 9
DDR2_ODT0: U5.T8(IO_L16N_16) ; also on sheet 9
DDR2_ODT1: U5.T9(IO_L18N_16) ; also on sheet 9
DDR2_RAS_B: U5.P6(IO_L11N_CC_16) ; also on sheet 9
DDR2_SCL: U5.P29(IO_L8N_CC_15) ; also on sheet 9 22
DDR2_SDA: U5.U28(IO_L16N_15) ; also on sheet 9 22
DDR2_WE_B: U5.T6(IO_L15N_16) ; also on sheet 9
DIP_SW0: R46.2 SW1.16(B1) ; also on sheet 7
DIP_SW1: R48.2 SW1.15(B2) ; also on sheet 7
DIP_SW2: R55.2 SW1.14(B3) ; also on sheet 7
DIP_SW3: R62.2 SW1.13(B4) ; also on sheet 7
DIP_SW4: R73.2 SW1.12(B5) ; also on sheet 7
DIP_SW5: R77.2 SW1.11(B6) ; also on sheet 7
DIP_SW6: R82.2 SW1.10(B7) ; also on sheet 7
DIP_SW7: R84.2 SW1.9(B8) ; also on sheet 7
DMD_TYPE_0: U5.AC15(IO_L0P_CC_RS1_2) ; also on sheet 11
DMD_TYPE_1: U5.AD15(IO_L0N_CC_RS0_2) ; also on sheet 11
DMD_TYPE_2: U5.AE22(IO_L1P_CC_A25_2) ; also on sheet 11
DMD_TYPE_3: U5.AE19(IO_L7N_D4_2) ; also on sheet 11
EXP1_DIFF_0_N: U5.AP32(IO_L19N_13) ; also on sheet 17
EXP1_DIFF_0_P: U5.AN32(IO_L19P_13) ; also on sheet 17
EXP1_DIFF_1_N: U5.AN33(IO_L18N_13) ; also on sheet 17
EXP1_DIFF_1_P: U5.AN34(IO_L18P_13) ; also on sheet 17
EXP1_DIFF_2_N: U5.AH33(IO_L12N_VRP_13) ; also on sheet 17
EXP1_DIFF_2_P: U5.AG33(IO_L12P_VRN_13) ; also on sheet 17
EXP1_DIFF_3_N: U5.AM32(IO_L17N_13) ; also on sheet 17
EXP1_DIFF_3_P: U5.AM33(IO_L17P_13) ; also on sheet 17
EXP1_DIFF_4_N: U5.AJ34(IO_L10N_CC_13) ; also on sheet 17
EXP1_DIFF_4_P: U5.AH34(IO_L10P_CC_13) ; also on sheet 17
EXP1_DIFF_5_N: U5.AD34(IO_L5N_13) ; also on sheet 17
EXP1_DIFF_5_P: U5.AC34(IO_L5P_13) ; also on sheet 17
EXP1_DIFF_6_N: U5.AE33(IO_L8N_CC_13) ; also on sheet 17
EXP1_DIFF_6_P: U5.AF33(IO_L8P_CC_13) ; also on sheet 17
EXP1_DIFF_7_N: U5.AB33(IO_L7N_13) ; also on sheet 17
EXP1_DIFF_7_P: U5.AC33(IO_L7P_13) ; also on sheet 17
EXP1_DIFF_8_N: U5.AK33(IO_L13N_13) ; also on sheet 17
EXP1_DIFF_8_P: U5.AK34(IO_L13P_13) ; also on sheet 17
EXP1_DIFF_9_N: U5.Y33(IO_L2N_13) ; also on sheet 17
EXP1_DIFF_9_P: U5.AA33(IO_L2P_13) ; also on sheet 17
EXP1_DIFF_10_N: U5.AL33(IO_L16N_13) ; also on sheet 17
EXP1_DIFF_10_P: U5.AL34(IO_L16P_13) ; also on sheet 17
EXP1_DIFF_11_N: U5.W32(IO_L4N_VREF_13) ; also on sheet 17
EXP1_DIFF_11_P: U5.Y32(IO_L4P_13) ; also on sheet 17
EXP1_DIFF_12_N: U5.AE32(IO_L11N_CC_13) ; also on sheet 17
EXP1_DIFF_12_P: U5.AD32(IO_L11P_CC_13) ; also on sheet 17
EXP1_DIFF_13_N: U5.Y34(IO_L3N_13) ; also on sheet 17
EXP1_DIFF_13_P: U5.AA34(IO_L3P_13) ; also on sheet 17
EXP1_DIFF_14_N: U5.V32(IO_L0N_13) ; also on sheet 17
EXP1_DIFF_14_P: U5.V33(IO_L0P_13) ; also on sheet 17
EXP1_DIFF_15_N: U5.V34(IO_L1N_13) ; also on sheet 17
EXP1_DIFF_15_P: U5.W34(IO_L1P_13) ; also on sheet 17
EXP1_DIFF_16_N: U5.T34(IO_L18N_11) ; also on sheet 17
EXP1_DIFF_16_P: U5.U33(IO_L18P_11) ; also on sheet 17
EXP1_DIFF_17_N: U5.AK32(IO_L15N_13) ; also on sheet 17
EXP1_DIFF_17_P: U5.AJ32(IO_L15P_13) ; also on sheet 17
EXP1_DIFF_18_N: U5.AE34(IO_L9N_CC_13) ; also on sheet 17
EXP1_DIFF_18_P: U5.AF34(IO_L9P_CC_13) ; also on sheet 17
EXP1_DIFF_19_N: U5.AH32(IO_L14N_VREF_13) ; also on sheet 17
EXP1_DIFF_19_P: U5.AG32(IO_L14P_13) ; also on sheet 17
EXP1_DIFF_20_N: U5.AB32(IO_L6N_13) ; also on sheet 17
EXP1_DIFF_20_P: U5.AC32(IO_L6P_13) ; also on sheet 17
EXP1_DIFF_21_N: U5.N32(IO_L15N_11) ; also on sheet 17
EXP1_DIFF_21_P: U5.P32(IO_L15P_11) ; also on sheet 17
EXP1_DIFF_CLK_OUT_N: U5.U32(IO_L19N_11) ; also on sheet 17
EXP1_DIFF_CLK_OUT_P: U5.U31(IO_L19P_11) ; also on sheet 17
EXP1_SE_IO_0: U5.C34(IO_L3P_11) ; also on sheet 17
EXP1_SE_IO_1: U5.A33(IO_L0N_11) ; also on sheet 17
EXP1_SE_IO_2: U5.D32(IO_L2N_11) ; also on sheet 17
EXP1_SE_IO_3: U5.B32(IO_L0P_11) ; also on sheet 17
EXP1_SE_IO_4: U5.D34(IO_L3N_11) ; also on sheet 17
EXP1_SE_IO_5: U5.B33(IO_L1P_11) ; also on sheet 17
EXP1_SE_IO_6: U5.E34(IO_L5N_11) ; also on sheet 17
EXP1_SE_IO_7: U5.C32(IO_L2P_11) ; also on sheet 17
EXP1_SE_IO_8: U5.G32(IO_L4P_11) ; also on sheet 17
EXP1_SE_IO_9: U5.H32(IO_L4N_VREF_11) ; also on sheet 17
EXP1_SE_IO_10: U5.F33(IO_L5P_11) ; also on sheet 17
EXP1_SE_IO_11: U5.C33(IO_L1N_11) ; also on sheet 17
EXP1_SE_IO_12_DIFF_22_P: U5.G33(IO_L7P_11) ; also on sheet 17
EXP1_SE_IO_13_DIFF_23_P: U5.K33(IO_L11P_CC_11) ; also on sheet 17
EXP1_SE_IO_14_DIFF_22_N: U5.F34(IO_L7N_11) ; also on sheet 17
EXP1_SE_IO_15_DIFF_23_N: U5.K32(IO_L11N_CC_11) ; also on sheet 17
EXP1_SE_IO_16_DIFF_24_P: U5.H34(IO_L9P_CC_11) ; also on sheet 17
EXP1_SE_IO_17_DIFF_25_P: U5.P34(IO_L14P_11) ; also on sheet 17
EXP1_SE_IO_18_DIFF_24_N: U5.J34(IO_L9N_CC_11) ; also on sheet 17
EXP1_SE_IO_19_DIFF_25_N: U5.N34(IO_L14N_VREF_11) ; also on sheet 17
EXP1_SE_IO_20_DIFF_26_P: U5.L34(IO_L10P_CC_11) ; also on sheet 17
EXP1_SE_IO_21_DIFF_27_P: U5.N33(IO_L12P_VRN_11) ; also on sheet 17
EXP1_SE_IO_22_DIFF_26_N: U5.K34(IO_L10N_CC_11) ; also on sheet 17
EXP1_SE_IO_23_DIFF_27_N: U5.M33(IO_L12N_VRP_11) ; also on sheet 17
EXP1_SE_IO_24_DIFF_28_P: U5.J32(IO_L8P_CC_11) ; also on sheet 17
EXP1_SE_IO_25_DIFF_29_P: U5.L33(IO_L13P_11) ; also on sheet 17
EXP1_SE_IO_26_DIFF_28_N: U5.H33(IO_L8N_CC_11) ; also on sheet 17
EXP1_SE_IO_27_DIFF_29_N: U5.M32(IO_L13N_11) ; also on sheet 17
EXP1_SE_IO_28: U5.E32(IO_L6P_11) ; also on sheet 17
EXP1_SE_IO_29: U5.E33(IO_L6N_11) ; also on sheet 17
EXP1_SE_IO_30_DIFF_30_P: U5.R33(IO_L17P_11) ; also on sheet 17
EXP1_SE_IO_31_DIFF_30_N: U5.R32(IO_L17N_11) ; also on sheet 17
EXP1_SE_IO_32_DIFF_31_P: U5.T33(IO_L16P_11) ; also on sheet 17
EXP1_SE_IO_33_DIFF_31_N: U5.R34(IO_L16N_11) ; also on sheet 17
EXP2_DIFF_0_N: U5.AL3(IO_L18N_14) ; also on sheet 18
EXP2_DIFF_0_P: U5.AM2(IO_L18P_14) ; also on sheet 18
EXP2_DIFF_1_N: U5.AM1(IO_L16N_14) ; also on sheet 18
EXP2_DIFF_1_P: U5.AL1(IO_L16P_14) ; also on sheet 18
EXP2_DIFF_2_N: U5.AP2(IO_L17N_14) ; also on sheet 18
EXP2_DIFF_2_P: U5.AN2(IO_L17P_14) ; also on sheet 18
EXP2_DIFF_3_N: U5.AN3(IO_L19N_14) ; also on sheet 18
EXP2_DIFF_3_P: U5.AM3(IO_L19P_14) ; also on sheet 18
EXP2_DIFF_4_N: U5.AD1(IO_L7N_14) ; also on sheet 18
EXP2_DIFF_4_P: U5.AC2(IO_L7P_14) ; also on sheet 18
EXP2_DIFF_5_N: U5.AK1(IO_L12N_VRP_14) ; also on sheet 18
EXP2_DIFF_5_P: U5.AJ1(IO_L12P_VRN_14) ; also on sheet 18
EXP2_DIFF_6_N: U5.AH3(IO_L15N_14) ; also on sheet 18
EXP2_DIFF_6_P: U5.AG3(IO_L15P_14) ; also on sheet 18
EXP2_DIFF_7_N: U5.AK3(IO_L13N_14) ; also on sheet 18
EXP2_DIFF_7_P: U5.AK2(IO_L13P_14) ; also on sheet 18
EXP2_DIFF_8_N: U5.AA1(IO_L5N_14) ; also on sheet 18
EXP2_DIFF_8_P: U5.AB1(IO_L5P_14) ; also on sheet 18
EXP2_DIFF_9_N: U5.AJ2(IO_L14N_VREF_14) ; also on sheet 18
EXP2_DIFF_9_P: U5.AH2(IO_L14P_14) ; also on sheet 18
EXP2_DIFF_10_N: U5.AD2(IO_L8N_CC_14) ; also on sheet 18
EXP2_DIFF_10_P: U5.AE2(IO_L8P_CC_14) ; also on sheet 18
EXP2_DIFF_11_N: U5.AE3(IO_L11N_CC_14) ; also on sheet 18
EXP2_DIFF_11_P: U5.AF3(IO_L11P_CC_14) ; also on sheet 18
EXP2_DIFF_12_N: U5.AG2(IO_L10N_CC_14) ; also on sheet 18
EXP2_DIFF_12_P: U5.AG1(IO_L10P_CC_14) ; also on sheet 18
EXP2_DIFF_13_N: U5.AE1(IO_L9N_CC_14) ; also on sheet 18
EXP2_DIFF_13_P: U5.AF1(IO_L9P_CC_14) ; also on sheet 18
EXP2_DIFF_14_N: U5.AA3(IO_L6N_14) ; also on sheet 18
EXP2_DIFF_14_P: U5.AB3(IO_L6P_14) ; also on sheet 18
EXP2_DIFF_15_N: U5.Y1(IO_L3N_14) ; also on sheet 18
EXP2_DIFF_15_P: U5.W2(IO_L3P_14) ; also on sheet 18
EXP2_DIFF_16_N: U5.V2(IO_L1N_14) ; also on sheet 18
EXP2_DIFF_16_P: U5.W1(IO_L1P_14) ; also on sheet 18
EXP2_DIFF_17_N: U5.U2(IO_L18N_12) ; also on sheet 18
EXP2_DIFF_17_P: U5.U1(IO_L18P_12) ; also on sheet 18
EXP2_DIFF_18_N: U5.V3(IO_L0N_14) ; also on sheet 18
EXP2_DIFF_18_P: U5.V4(IO_L0P_14) ; also on sheet 18
EXP2_DIFF_19_N: U5.T3(IO_L19N_12) ; also on sheet 18
EXP2_DIFF_19_P: U5.U3(IO_L19P_12) ; also on sheet 18
EXP2_DIFF_20_N: U5.L1(IO_L12N_VRP_12) ; also on sheet 18
EXP2_DIFF_20_P: U5.M1(IO_L12P_VRN_12) ; also on sheet 18
EXP2_DIFF_21_N: U5.N3(IO_L13N_12) ; also on sheet 18
EXP2_DIFF_21_P: U5.M3(IO_L13P_12) ; also on sheet 18
EXP2_DIFF_CLK_OUT_N: U5.AB2(IO_L4N_VREF_14) ; also on sheet 18
EXP2_DIFF_CLK_OUT_P: U5.AC3(IO_L4P_14) ; also on sheet 18
EXP2_SE_IO_0: U5.B3(IO_L0N_12) ; also on sheet 18
EXP2_SE_IO_1: U5.D1(IO_L3N_12) ; also on sheet 18
EXP2_SE_IO_2: U5.B1(IO_L1N_12) ; also on sheet 18
EXP2_SE_IO_3: U5.D2(IO_L3P_12) ; also on sheet 18
EXP2_SE_IO_4: U5.B2(IO_L2N_12) ; also on sheet 18
EXP2_SE_IO_5: U5.J2(IO_L9P_CC_12) ; also on sheet 18
EXP2_SE_IO_6: U5.A3(IO_L0P_12) ; also on sheet 18
EXP2_SE_IO_7: U5.J1(IO_L10N_CC_12) ; also on sheet 18
EXP2_SE_IO_8: U5.C2(IO_L1P_12) ; also on sheet 18
EXP2_SE_IO_9: U5.K1(IO_L10P_CC_12) ; also on sheet 18
EXP2_SE_IO_10: U5.C3(IO_L2P_12) ; also on sheet 18
EXP2_SE_IO_11: U5.K2(IO_L9N_CC_12) ; also on sheet 18
EXP2_SE_IO_12_DIFF_22_P: U5.E2(IO_L5P_12) ; also on sheet 18
EXP2_SE_IO_13_DIFF_23_P: U5.H2(IO_L11P_CC_12) ; also on sheet 18
EXP2_SE_IO_14_DIFF_22_N: U5.E1(IO_L5N_12) ; also on sheet 18
EXP2_SE_IO_15_DIFF_23_N: U5.H3(IO_L11N_CC_12) ; also on sheet 18
EXP2_SE_IO_16_DIFF_24_P: U5.E3(IO_L4P_12) ; also on sheet 18
EXP2_SE_IO_17_DIFF_25_P: U5.P2(IO_L14P_12) ; also on sheet 18
EXP2_SE_IO_18_DIFF_24_N: U5.F3(IO_L4N_VREF_12) ; also on sheet 18
EXP2_SE_IO_19_DIFF_25_N: U5.R3(IO_L14N_VREF_12) ; also on sheet 18
EXP2_SE_IO_20_DIFF_26_P: U5.F1(IO_L7P_12) ; also on sheet 18
EXP2_SE_IO_21_DIFF_27_P: U5.T1(IO_L16P_12) ; also on sheet 18
EXP2_SE_IO_22_DIFF_26_N: U5.G1(IO_L7N_12) ; also on sheet 18
EXP2_SE_IO_23_DIFF_27_N: U5.R1(IO_L16N_12) ; also on sheet 18
EXP2_SE_IO_24_DIFF_28_P: U5.G3(IO_L6P_12) ; also on sheet 18
EXP2_SE_IO_25_DIFF_29_P: U5.K3(IO_L8P_CC_12) ; also on sheet 18
EXP2_SE_IO_26_DIFF_28_N: U5.G2(IO_L6N_12) ; also on sheet 18
EXP2_SE_IO_27_DIFF_29_N: U5.L3(IO_L8N_CC_12) ; also on sheet 18
EXP2_SE_IO_28: U5.Y2(IO_L2N_14) ; also on sheet 18
EXP2_SE_IO_29: U5.Y3(IO_L2P_14) ; also on sheet 18
EXP2_SE_IO_30_DIFF_30_P: U5.N2(IO_L15P_12) ; also on sheet 18
EXP2_SE_IO_31_DIFF_30_N: U5.M2(IO_L15N_12) ; also on sheet 18
EXP2_SE_IO_32_DIFF_31_P: U5.P1(IO_L17P_12) ; also on sheet 18
EXP2_SE_IO_33_DIFF_31_N: U5.R2(IO_L17N_12) ; also on sheet 18
FINISHED: U5.T25(IO_L19N_15) ; also on sheet 8
FLASH_CS#: U5.U25(IO_L19P_15) ; also on sheet 7
GPIFADR0/TST_HDR_BY2_0: U5.K31(IO_L9P_CC_15) ; also on sheet 21
GPIFADR1/TST_HDR_BY2_1: U5.L31(IO_L9N_CC_15) ; also on sheet 21
GPIFADR2/TST_HDR_BY2_2: U5.P31(IO_L10P_CC_15) ; also on sheet 21
GPIFADR3/TST_HDR_BY2_3: U5.P30(IO_L10N_CC_15) ; also on sheet 21
GPIFADR4/TST_HDR_BY2_4: U5.N30(IO_L11P_CC_15) ; also on sheet 21
GPIFADR5/TST_HDR_BY2_5: U5.M31(IO_L11N_CC_15) ; also on sheet 21
GPIFADR6/TST_HDR_BY2_6: U5.R28(IO_L12P_VRN_15) ; also on sheet 21
GPIFADR7/TST_HDR_BY2_7: U5.R29(IO_L12N_VRP_15) ; also on sheet 21
GPIFADR8/TST_HDR_BY3_0: U5.T31(IO_L13P_15) ; also on sheet 21
GPIO_A0: J6.9 ; also on sheet 7
GPIO_A1: J6.8 ; also on sheet 7
GPIO_A2: J6.7 ; also on sheet 7
GPIO_A3: J6.6 ; also on sheet 7
GPIO_A4: J6.5 ; also on sheet 7
GPIO_A5: J6.4 ; also on sheet 7
GPIO_A6: J6.3 ; also on sheet 7
GPIO_A7: J6.2 ; also on sheet 7
LED0: D11.2(CATHODE) ; also on sheet 7
LED1: D12.2(CATHODE) ; also on sheet 7
OVERVOTLAGE_G: Q1.4(G) U15.4(G)
POWER_IN_F: F5.2 Q1.5(D5) Q1.6(D6) Q1.7(D7) Q1.8(D8) U15.5(VIN)
POWER_STANDBY#: R107.1 R265.1 SW4.2 ; also on sheet 19 20
ROWMD_0: R719.1 U5.AE13(IO_L4N_VREF_FOE_B_MOSI_2) ; also on sheet 11
ROWMD_1: U5.AD20(IO_L5P_FWE_B_2) ; also on sheet 11
RST2BLKZ: U5.AE23(IO_L1N_CC_A24_2) ; also on sheet 11
SPI_FLASH_FS0: R714.2 TP201.1(TP) U5.AC20(IO_L9N_D0_FS0_2)
SPI_FLASH_FS1: R716.1 U5.AC19(IO_L9P_D1_FS1_2)
SPI_FLASH_FS2: R715.2 U5.AE17(IO_L8N_D2_FS2_2)
STEPVCC: R724.1 U5.AE12(IO_L4P_FCS_B_2) ; also on sheet 11
U30_EN: J21.2 R742.1 U30.2(\\~{OE})
U31_EN: J22.2 R743.1 U31.2(\\~{OE})
USB_CTRL0/TST_HDR_BY3_1: U5.R31(IO_L13N_15) ; also on sheet 21
USB_CTRL1/TST_HDR_BY3_2: U5.U30(IO_L14P_15) ; also on sheet 21
USB_CTRL2/TST_HDR_BY3_3: U5.T30(IO_L14N_VREF_15) ; also on sheet 21
USB_CTRL3/TST_HDR_BY3_4: U5.T28(IO_L15P_15) ; also on sheet 21
USB_FD0/TST_HDR_BY0_0: U5.H29(IO_L2P_15) ; also on sheet 21
USB_FD1/TST_HDR_BY0_1: U5.H30(IO_L5P_15) ; also on sheet 21
USB_FD2/TST_HDR_BY0_2: U5.J31(IO_L6N_15) ; also on sheet 21
USB_FD3/TST_HDR_BY0_3: U5.G30(IO_L1P_15) ; also on sheet 21
USB_FD4/TST_HDR_BY0_4: U5.J30(IO_L6P_15) ; also on sheet 21
USB_FD5/TST_HDR_BY0_5: U5.G31(IO_L5N_15) ; also on sheet 21
USB_FD6/TST_HDR_BY0_6: U5.J29(IO_L2N_15) ; also on sheet 21
USB_FD7/TST_HDR_BY0_7: U5.F29(IO_L0N_15) ; also on sheet 21
USB_FD8/TST_HDR_BY1_0: U5.K29(IO_L4P_15) ; also on sheet 21
USB_FD9/TST_HDR_BY1_1: U5.F30(IO_L1N_15) ; also on sheet 21
USB_FD10/TST_HDR_BY1_2: U5.L30(IO_L7P_15) ; also on sheet 21
USB_FD11/TST_HDR_BY1_3: U5.F31(IO_L3P_15) ; also on sheet 21
USB_FD12/TST_HDR_BY1_4: U5.L29(IO_L4N_VREF_15) ; also on sheet 21
USB_FD13/TST_HDR_BY1_5: U5.E29(IO_L0P_15) ; also on sheet 21
USB_FD14/TST_HDR_BY1_6: U5.E31(IO_L3N_15) ; also on sheet 21
USB_FD15/TST_HDR_BY1_7: U5.M30(IO_L7N_15) ; also on sheet 21
USB_FPGA_RESET/TST_HDR_BY3_5: U5.T29(IO_L15N_15) ; also on sheet 21
USB_GPIO_B0: J3.9 ; also on sheet 22
USB_GPIO_B1: J3.8 ; also on sheet 22
USB_GPIO_B2: J3.7 ; also on sheet 22
USB_GPIO_B3: J3.6 ; also on sheet 22
USB_GPIO_B4: J3.5 ; also on sheet 22
USB_GPIO_B5: J3.4 ; also on sheet 22
USB_GPIO_B6: J3.3 ; also on sheet 22
USB_GPIO_B7: J3.2 ; also on sheet 22
USB_IF_CLK/TEST_CLK_0: U5.N29(IO_L8P_CC_15) ; also on sheet 21 22
USB_INT5#/TST_HDR_BY3_6: U5.U27(IO_L16P_15) ; also on sheet 21
USB_RDY0: U5.R26(IO_L17P_15) ; also on sheet 22
USB_RDY1: U5.R27(IO_L17N_15) ; also on sheet 22
USB_RDY2: U5.U26(IO_L18P_15) ; also on sheet 22
VLED0: D9.2(CATHODE) ; also on sheet 11
VLED1: D10.2(CATHODE) ; also on sheet 11
WDT_ENBLZ: U5.AF15(IO_L2P_A23_2) ; also on sheet 11
XCF_CCLK: R722.2 ; also on sheet 8
XCF_D0: R718.2 ; also on sheet 8
XCF_V5_CCLK: R721.1 R722.1 ; also on sheet 8
XCF_V5_D0: R717.1 R718.1 ; also on sheet 8
N9169270: D9.1(ANODE) R112.2
N9169274: D10.1(ANODE) R114.2
N9169280: D11.1(ANODE) R118.2
N9169288: D12.1(ANODE) R119.2
N17689429: R132.1 U5.H8(IO_L12N_VRP_20)
N37418856: R128.2 U5.H7(IO_L12P_VRN_20)
N39502832: F5.1 J12.1 J18.3(1) J18.4(3)
N41021981: R123.1 U5.M27(IO_L12N_VRP_19)
N41041536: R122.2 U5.N27(IO_L12P_VRN_19)
N55969993: R21.2 U5.R9(IO_L12P_VRN_16)
N55982593: R23.1 U5.R8(IO_L12N_VRP_16)
N59183238: R108.2 R265.2 SW4.1
N62338276: J20.1 R726.2
N62338291: J20.4 TP202.1
N62338293: J20.3 TP203.1
N62338308: J20.6 TP204.1
N62338310: J20.5 R727.2
N62338334: J20.8 R728.1
N62338336: J20.7 R729.2
N62338353: J20.9 R730.2
N62338937: R731.2 U27.3(WP#/IO2)
N62338939: R732.2 U27.7(IO3/RESET#)

Not connected (* = marked no-connect by the designer): U5 E26(IO_L11P_CC_19)* E27(IO_L11N_CC_19)* K8(IO_L11N_CC_20)* L8(IO_L11P_CC_20)* T11(IO_L19N_16)* T26(IO_L18N_15)*; U15 1(NC1)* 3(NC3)*

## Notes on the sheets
sheet 1
- Important Notice and Disclaimer
  TI PROVIDES TECHNICAL AND RELIABILITY DATA (INCLUDING DATASHEETS), DESIGN RESOURCES (INCLUDING REFERENCE DESIGNS), APPLICATION OR OTHER DESIGN ADVICE, WEB TOOLS, SAFETY
  INFORMATION, AND OTHER RESOURCES “AS IS” AND WITH ALL FAULTS, AND DISCLAIMS ALL WARRANTIES, EXPRESS AND IMPLIED, INCLUDING WITHOUT LIMITATION ANY IMPLIED WARRANTIES OF
  MERCHANTABILITY, FITNESS FOR A PARTICULAR PURPOSE OR NON-INFRINGEMENT OF THIRD PARTY INTELLECTUAL PROPERTY RIGHTS.
  These resources are intended for skilled developers designing with TI products. You are solely responsible for (1) selecting the appropriate TI products for your application, (2) designing, validating and testing your application, and (3)
  ensuring your application meets applicable standards, and any other safety, security, regulatory or other requirements.
  These resources are subject to change without notice. TI grants you permission to use these resources only for development of an application that uses the TI products described in the resource. Other reproduction and display of
  these resources is prohibited. No license is granted to any other TI intellectual property right or to any third party intellectual property right. TI disclaims responsibility for, and you will fully indemnify TI and its representatives against,
  any claims, damages, costs, losses, and liabilities arising out of your use of these resources.
  TI’s products are provided subject to TI’s Terms of Sale or other applicable terms available either on ti.com or provided in conjunction with such TI products. TI’s provision of these resources does not expand or otherwise alter TI’s
  applicable warranties or warranty disclaimers for TI products.
  TI objects to and rejects any additional or different terms you may have proposed.
- (C) COPYRIGHT 2023
         Texas Instruments
        All Rights Reserved
- DLP010
sheet 2
- NOTES:
- 1. The netname "VCC_1P8V" represents connection to the +1.8V digital power plane.
- 2. The netname "VCC_2P5V" represents connection to the +2.5V digital power plane.
- 3. The netname "VCC_3P3V" represents connection to the +3.3V digital power plane.
- 4. The netname "GND" represents connection to the ground plane.
- 5. A "#" suffix on a signal plane indicates an active low signal.
- 6. All components with designators "U", "Q", and "D" are electrostatic discharge sensitive.
- 7. All resistor values are in ohms unless otherwise specified.
- 8. All capacitor values in microfarads unless otherwise specified.
- 9. Bluewire cicuit modifications are noted by dashed outlines.
- Default Jumper Settings
- J10 1-2
  	J5 2-3
  	J3 2-3,5-6,8-9,11-12,14-15
- REVISIONS:
- B: Update to replace EOL 32 bit buffer (U20) and add SPI Config Flash Devices (U24 and U27) to DLPC410
- P.5 - Added SPI PROM Circuit: R714 - R730, J20, U27, and C291.
      - Added FS0, FS1, and FS2 connections to U5B
      - Added XCF_V5_D0, XCF_D0, XCF_V5_CCLK, XCF_CCLK, and V5_CS_B connections
- P.7 - U5S: Changed VCC0_1 and VCC0_2 (Bank 0 I/O Voltage) from 2.5V to 3.3V.
      - U5A: Added V5_CS_B connection.
      - U10: Changed VCCJ, VCC01, VCC02, VCC03, VCC04 pins from 2.5V to 3.3V.
             Changed J4 pin 1 from 2.5V to 3.3V.
             Added XCF_D0 and XCF_CCLK connections.
      - U21: Changed VCC and S0 pins from 2.5V to 3.3V.
             Changed R156 pull up on S1 from 2.5V to 3.3V.
             Added XCF_V5_CCLK and XCF_V5_D0 connections.
      - Changed R158, R131, R134, R136, R37, R27, R1, R15 pull up connections from 2.5V to 3.3V.
      - Added R737 connection to bypass XCF16 PROM
      - Added R734 and R735 connections.
- CONTENTS :
- TITLE PAGE
- 1
- P.10 - U11B: Added FSO, FS1, and FS2 connections.
               Added R278 and R280 resistors for SPI MODE Selection.
- BLOCK DIAGRAM
- 2
- UI CONNECTORS
- 3
- P.11 - Added SPI PROM Circuit: U24, R266-R277, R710-R712, and C288.
       - U11N: Changed VCC0_1 and VCC0_2 (Bank 0 I/O Voltage) from 2.5V to 3.3V.
       - U11A: Changed R699 pull up on VBATT_0 from 2.5V to 3.3V
               Changed R698 pull up on HSWAPEN from 2.5V to 3.3V.
               Added R710 and R711.
               Added DONE_DDC_PROM and INTB_DDC_PROM connections.
       - U8: Changed VCCJ, VCC01, VCC02, VCC03, VCC04 pins from 2.5V to 3.3V.
             Changed J11 pin 1 from 2.5V to 3.3V.
             Added PROM_CCK_DDC, PROM_D0_DDC, INTB_DDC_PROM, and DONE_DDC_PROM connections.
       - Changed R83, R85, R86, R54, R58, R51, R56 pull up connections from 2.5V to 3.3V
       - Added R736 connection to bypass XCF16 PROM
- APPS FPGA 1
- 4
- APPS FPGA 2
- 5
- APPS FPGA 3
- 6
- APPS FPGA 4
- 7
- P.20 - Removed U20 and replaced with U25 and U26
- DDR2 SO-DIMM
- 8
- P.21 - Changed U19 to a more available part.
- DLPC410 1
- 9
- C: Update for SPI Signal Level Shifting between 3.3V SPI Config Flash Devices (U24 and U27) and 2.5V interface to APPS FPGA and DLPC410.
- DLPC410 2
- 10
- P.5 - Added Level Shift Circuit: U30, U31, J21, J22, R742, and R743
- DLPC410 3
- 11
- P.7 - DNI U10 PROM
- DLPA200 A
- 12
- P.11 - Added Level Shift Circuit: U28, U29, J23, J24, R744, and R745
       - DNI U8 PROM
- DLPA200 B
- 13
- DMD FLEX A
- 14
- DMD FLEX B
- 15
- EXP CONNECTOR 1
- 16
- EXP CONNECTOR 2
- 17
- POWER 1
- 18
- POWER 2
- 19
- TEST HEADERS
- 20
- USB CONTROLLER
- 21
- UNUSED PINS
- 22
- 2509486
- 0314CP
sheet 3
- DATA[63:00]
- MBRST
- 64 BIT DDR2
  SO-DIMM
- NOTE: AT45DB642D is obsolete. If
  customers want flash functionality,
  the customer must identify and
  implement a different flash solution.
- DLPA200 A
- DAD_INIT, DAD_MODE[1:0]
  DAD_ADDR [3:0], IRQ/(OMIT)
  STROBE, SEL[1:0], DAD_OEZ_A
- ADD & CTRL
- PAGE 12
- PAGE 08
- Flash
  AT45DB642D
  8 x 13.4
- 2.5V GPIO A
- PAGE 06
- PAGE 03
- SCPEN_A
- DMD FLEX
  CONNECTOR A
- FLASH_RDY, RSTZ,
  WPZ, CSZ, SER,
  SCK, SI, SO
- FLASH_IO[7:0]
- SCP
- SCPEN, SCP
- PAGE 14
- DATA_A[15:00] lvds
  DCLK lvds
  SCTRL_A lvds
- 50Mhz OSC
- 20
- 16
- 12
- 14
- 18
- 22
- DATA_B[15:00] lvds,
  DCLK lvds,
  SCTRL_B lvds
- DDC_DINA[15:00] lvds
  DDC_DINB[15:00] lvds
  DDC_DINC[15:00] lvds
  DDC_DIND[15:00] lvds
- PAGE 06
- Application FPGA
- DLPC410
- 3
- 1
- PAGE
  04,05,06,07
- 2
- 4
- CR122
  BATTERY HOLDER
- DATA_C[15:00] lvds, DCLK lvds, SCTRL_C lvds
- Dclk<A B C D> lvds
  Dvalid<A B C D> lvds
- PAGE 09,10,11
- DATA_D[15:00] lvds
  DCLK lvds
  SCTRL_D lvds
- 19
- 15
- 11
- 13
- 17
- 21
- PAGE 07
- DAD_INIT, DAD_MODE[1:0]
  DAD_ADDR [3:0], IRQ/(OMIT)
  STROBE, SEL[1:0], DAD_OEZ_B
- SCPEN, SCP
- USB_FD[15:00]
- DMD_TYPE, Rowmd, rowad
  Stepvcc, ns_flip, comp_data
  blkmd, blkad,init_acitve, wdt_enable
- DMD FLEX
  CONNECTOR B
- GPIFADR[8:0]
- USB_CTRL[5:0],
  USB_RDY[2:0], IFCLK,
- SCPEN_B
- SCP
- PAGE 15
- APPSFPGA PROM
  SPI Config
  Flash
- DLPR410 PROM
  SPI Config
  Flash
- USB Controller
  CY7C68013A
- EXP Connectors
- PAGE 16, 17
- PAGE 07
- PAGE 11
- PAGE 21
- JTAG HEADER
- PAGE 07
- MBRST
- DLPA200 B
- MICTOR
  TEST HEADER
  J10
- MICTOR
  TEST HEADER
  J9
- PAGE 13
- USB GPIO B
- PAGE 20
- PAGE 20
- PAGE 03
- Power Regulators and Startup Sequence
- VOLTAGE
  REGULATORS
- 12V 0.5A
- 2.5V 6A
- 3.3V 3A
- 12V, 3.3V, 2.5V,
  1.8V, 1.0V
- 5 VOLT POWER
  INPUT JACK
- 5V
- PAGE 03
- 1.0V 3A
- 1.8V 6A
- 0.9V 1A
- BLOCK DIAGRAM
- DLP010
- PAGE 18,19
sheet 4
- APPSFPGA LOGIC RESET
- GPIO_A
- DMD_MIRROR FLOAT
- GPIO_B
- POWER STANDBY
- NOTE: Do Not Install
- 5V POWER IN
- OVER VOLTAGE PROTECTION
- Input Power
- UI CONNECTORS
- DLP010
sheet 5
- 2.5V/3.3V
- 2.5V/3.3V
- 2.5V/3.3V
- 2.5V/3.3V
- 3.3V
- APPS FPGA - 1
- DLP010
sheet 6
- 1.8V
- 1.8V
- 1.8V
- 1.8V / 2.5V
- SPI CONFIG FLASH
- Place jumper on J21 and J22 to program
  U27 with Cheetah SPI Programmer.
- NOTE: Do Not Install
- MOSI
- NOTE: Do Not Install
- FCS_B
- NOTE: Do Not Install
- SPI FLASH MODE: 0x03
  FS0: 1
  FS1: 0
  FS2: 1
- APPS FPGA - 2
- DLP010
